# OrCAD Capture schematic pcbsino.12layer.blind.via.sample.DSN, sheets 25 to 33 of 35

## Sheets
25 Pg18: Gbit Ethernet #1: size C
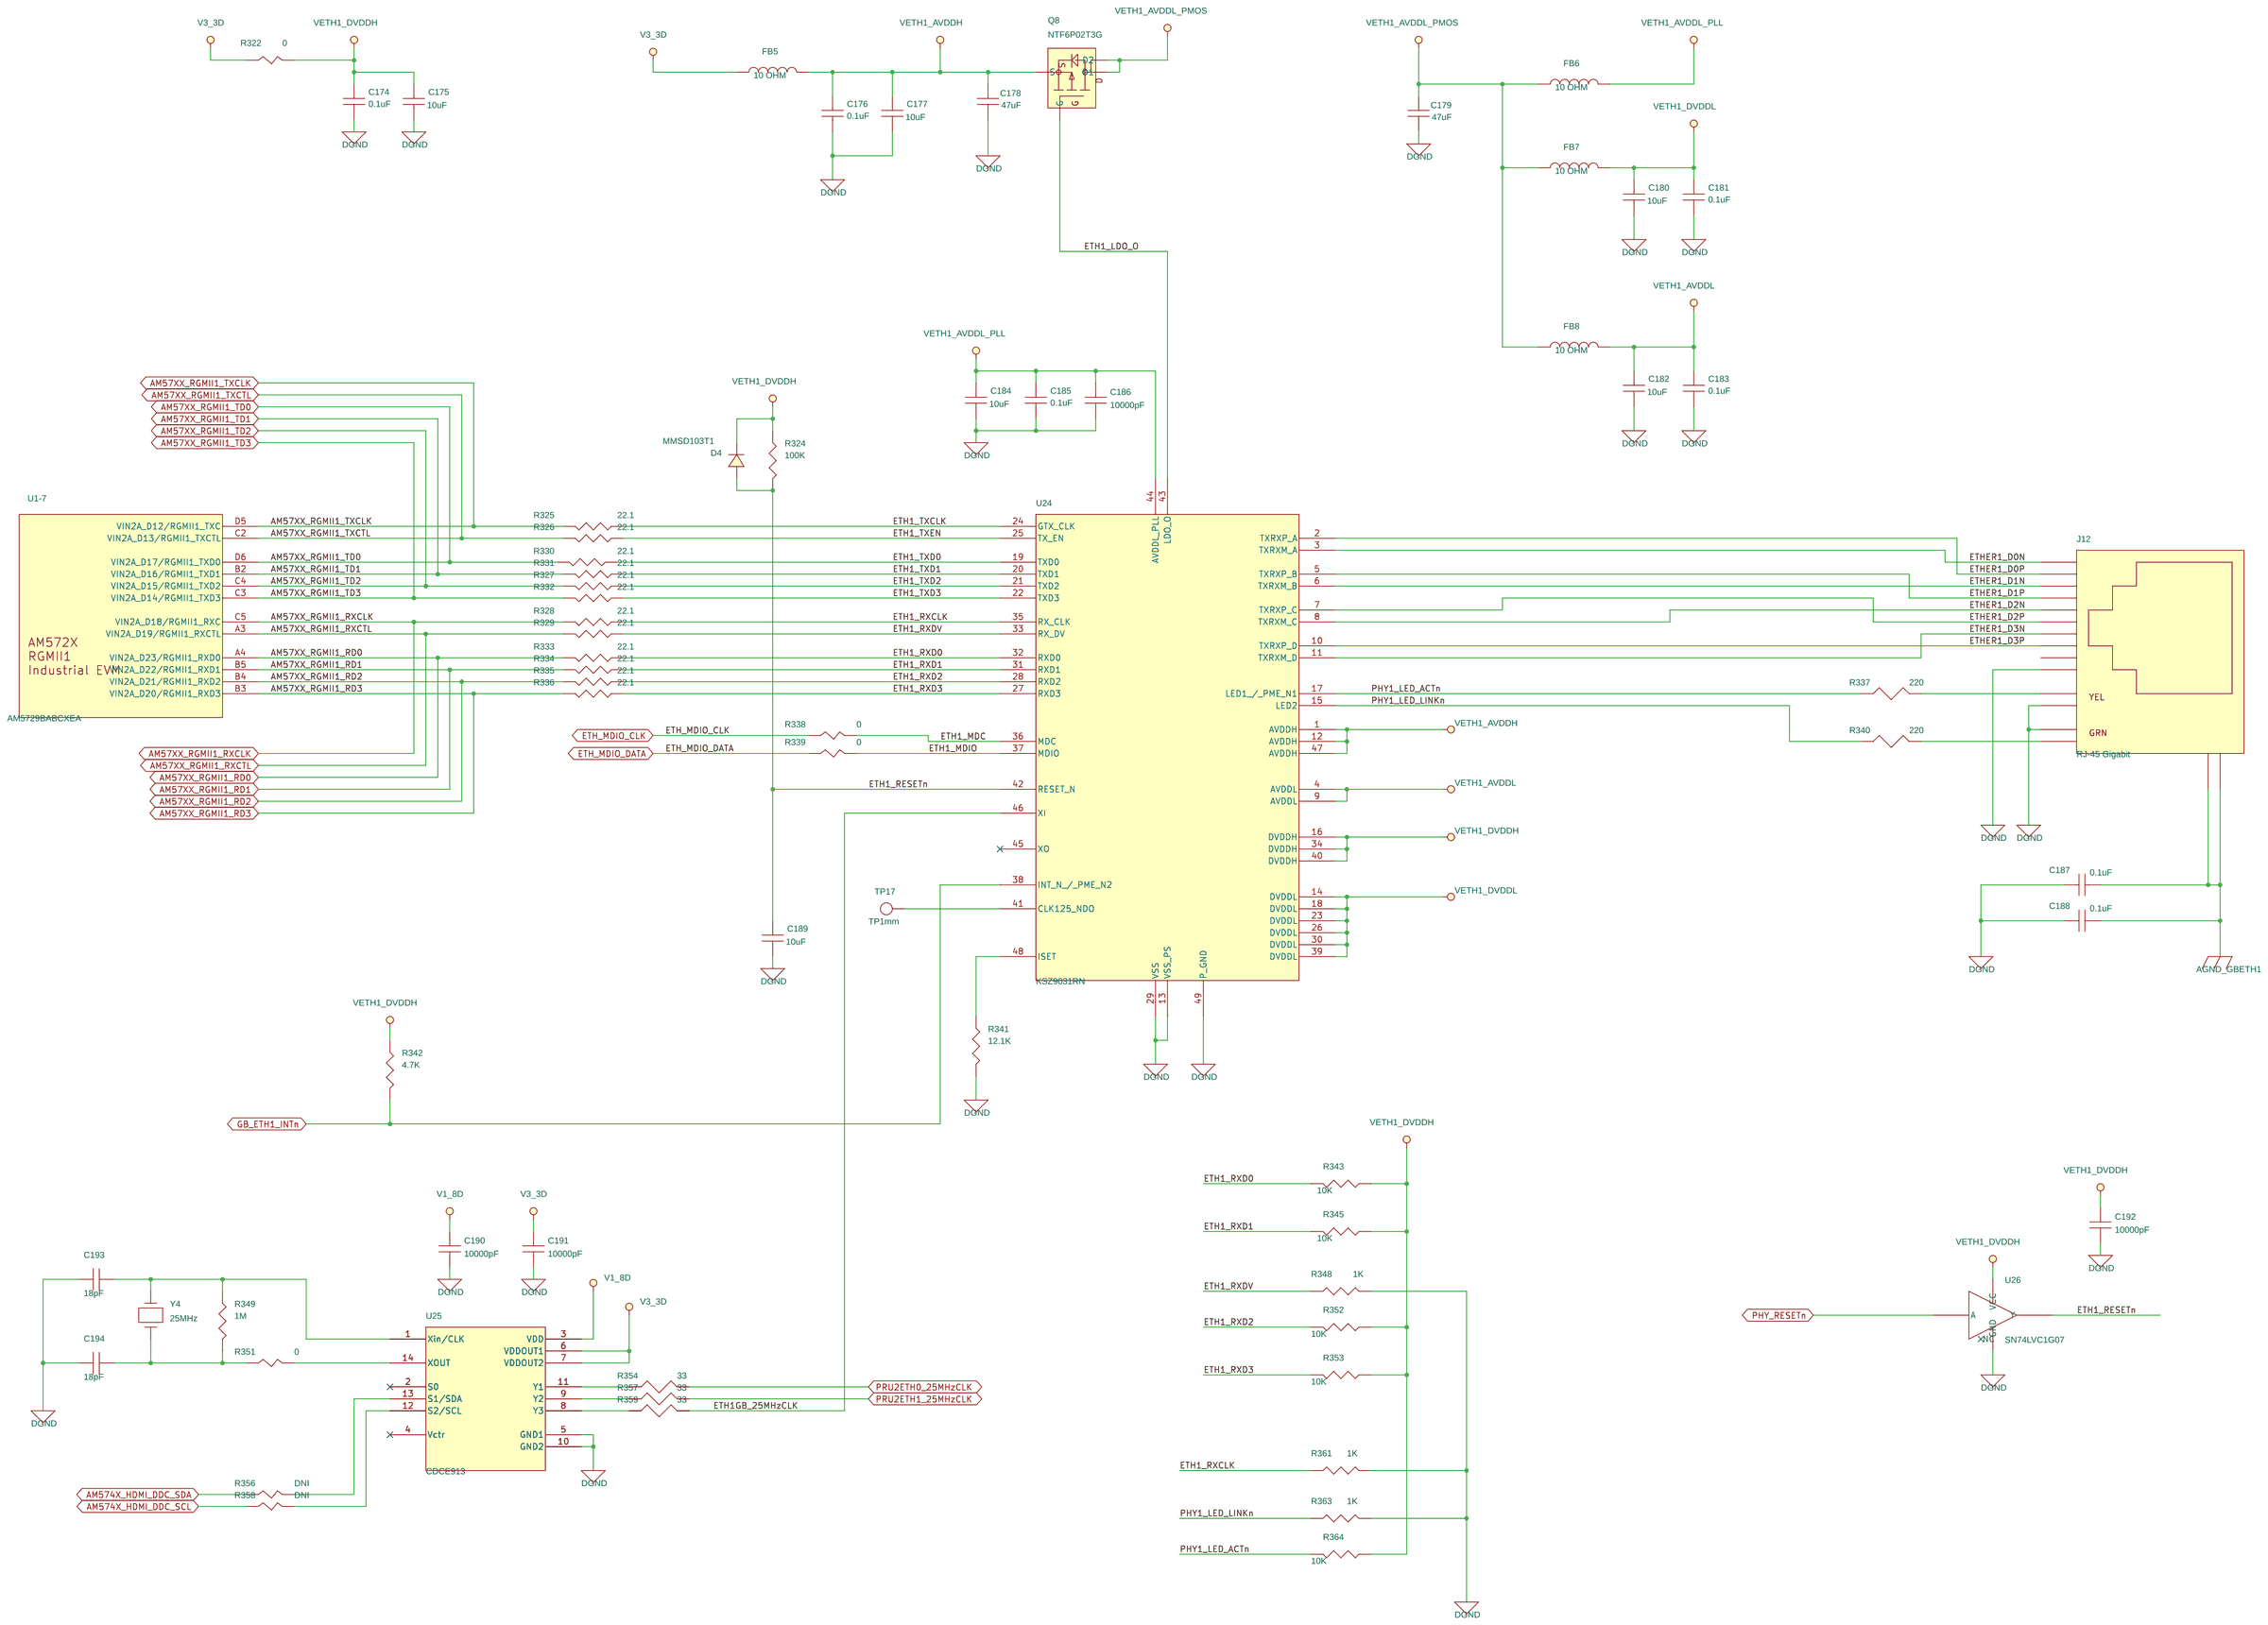
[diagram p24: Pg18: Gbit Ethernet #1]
26 Pg14: ICSS2 Ethernet 1: size C
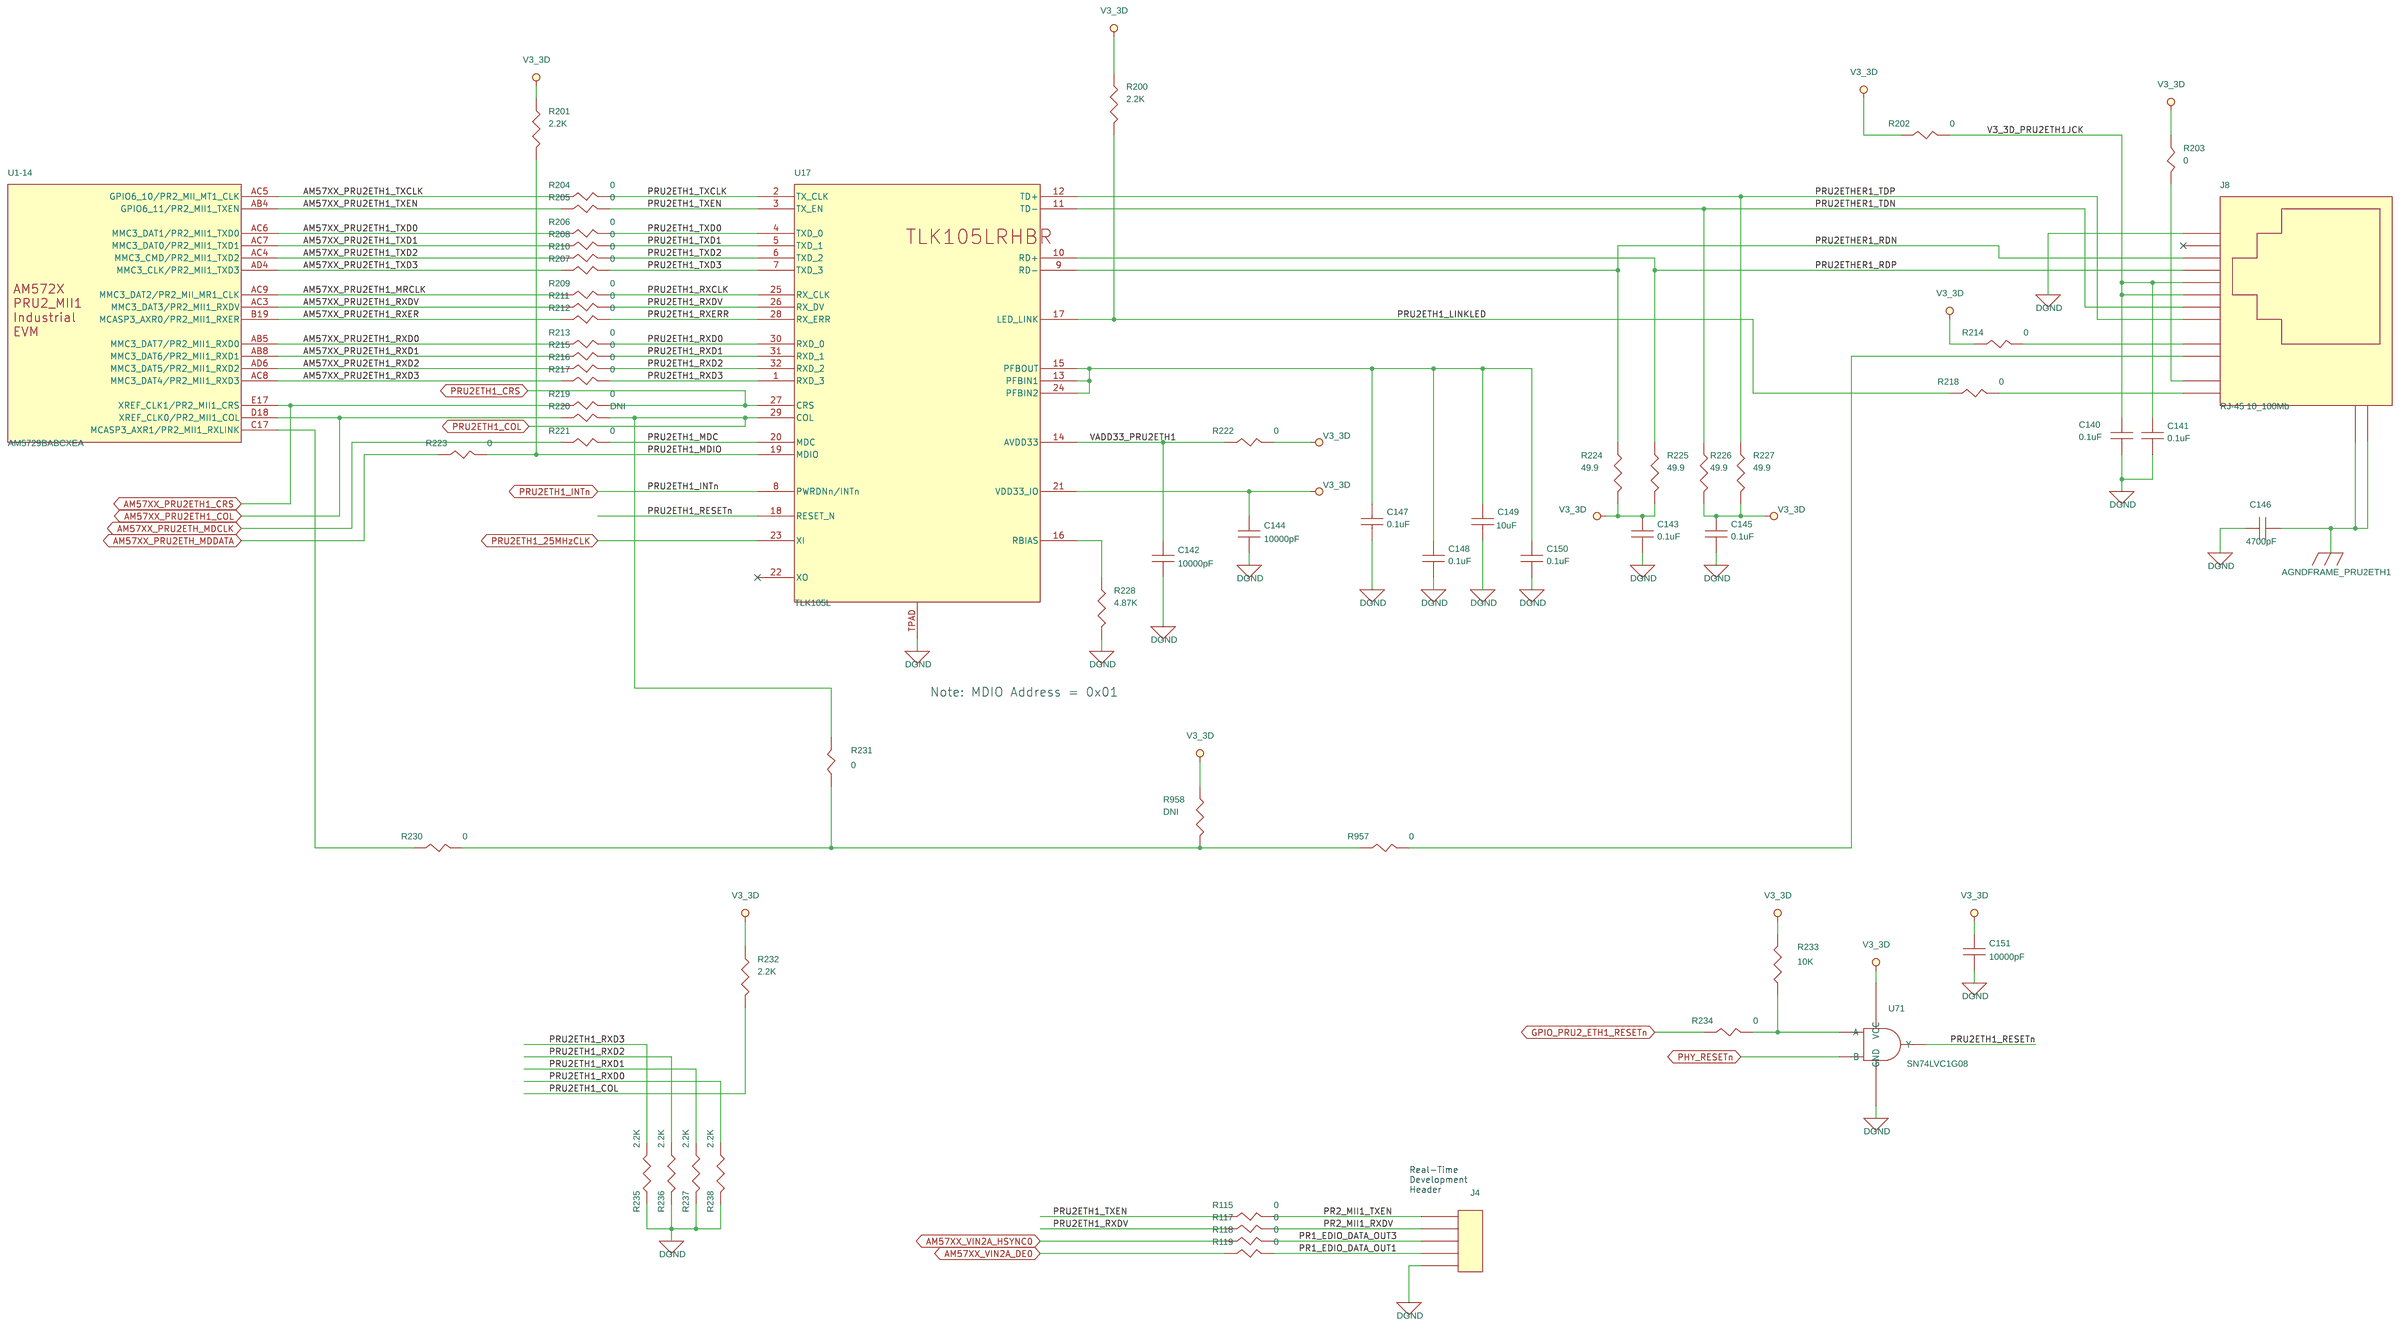
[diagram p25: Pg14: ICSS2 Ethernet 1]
27 Pg13: ICSS2 Ethernet 0: size C
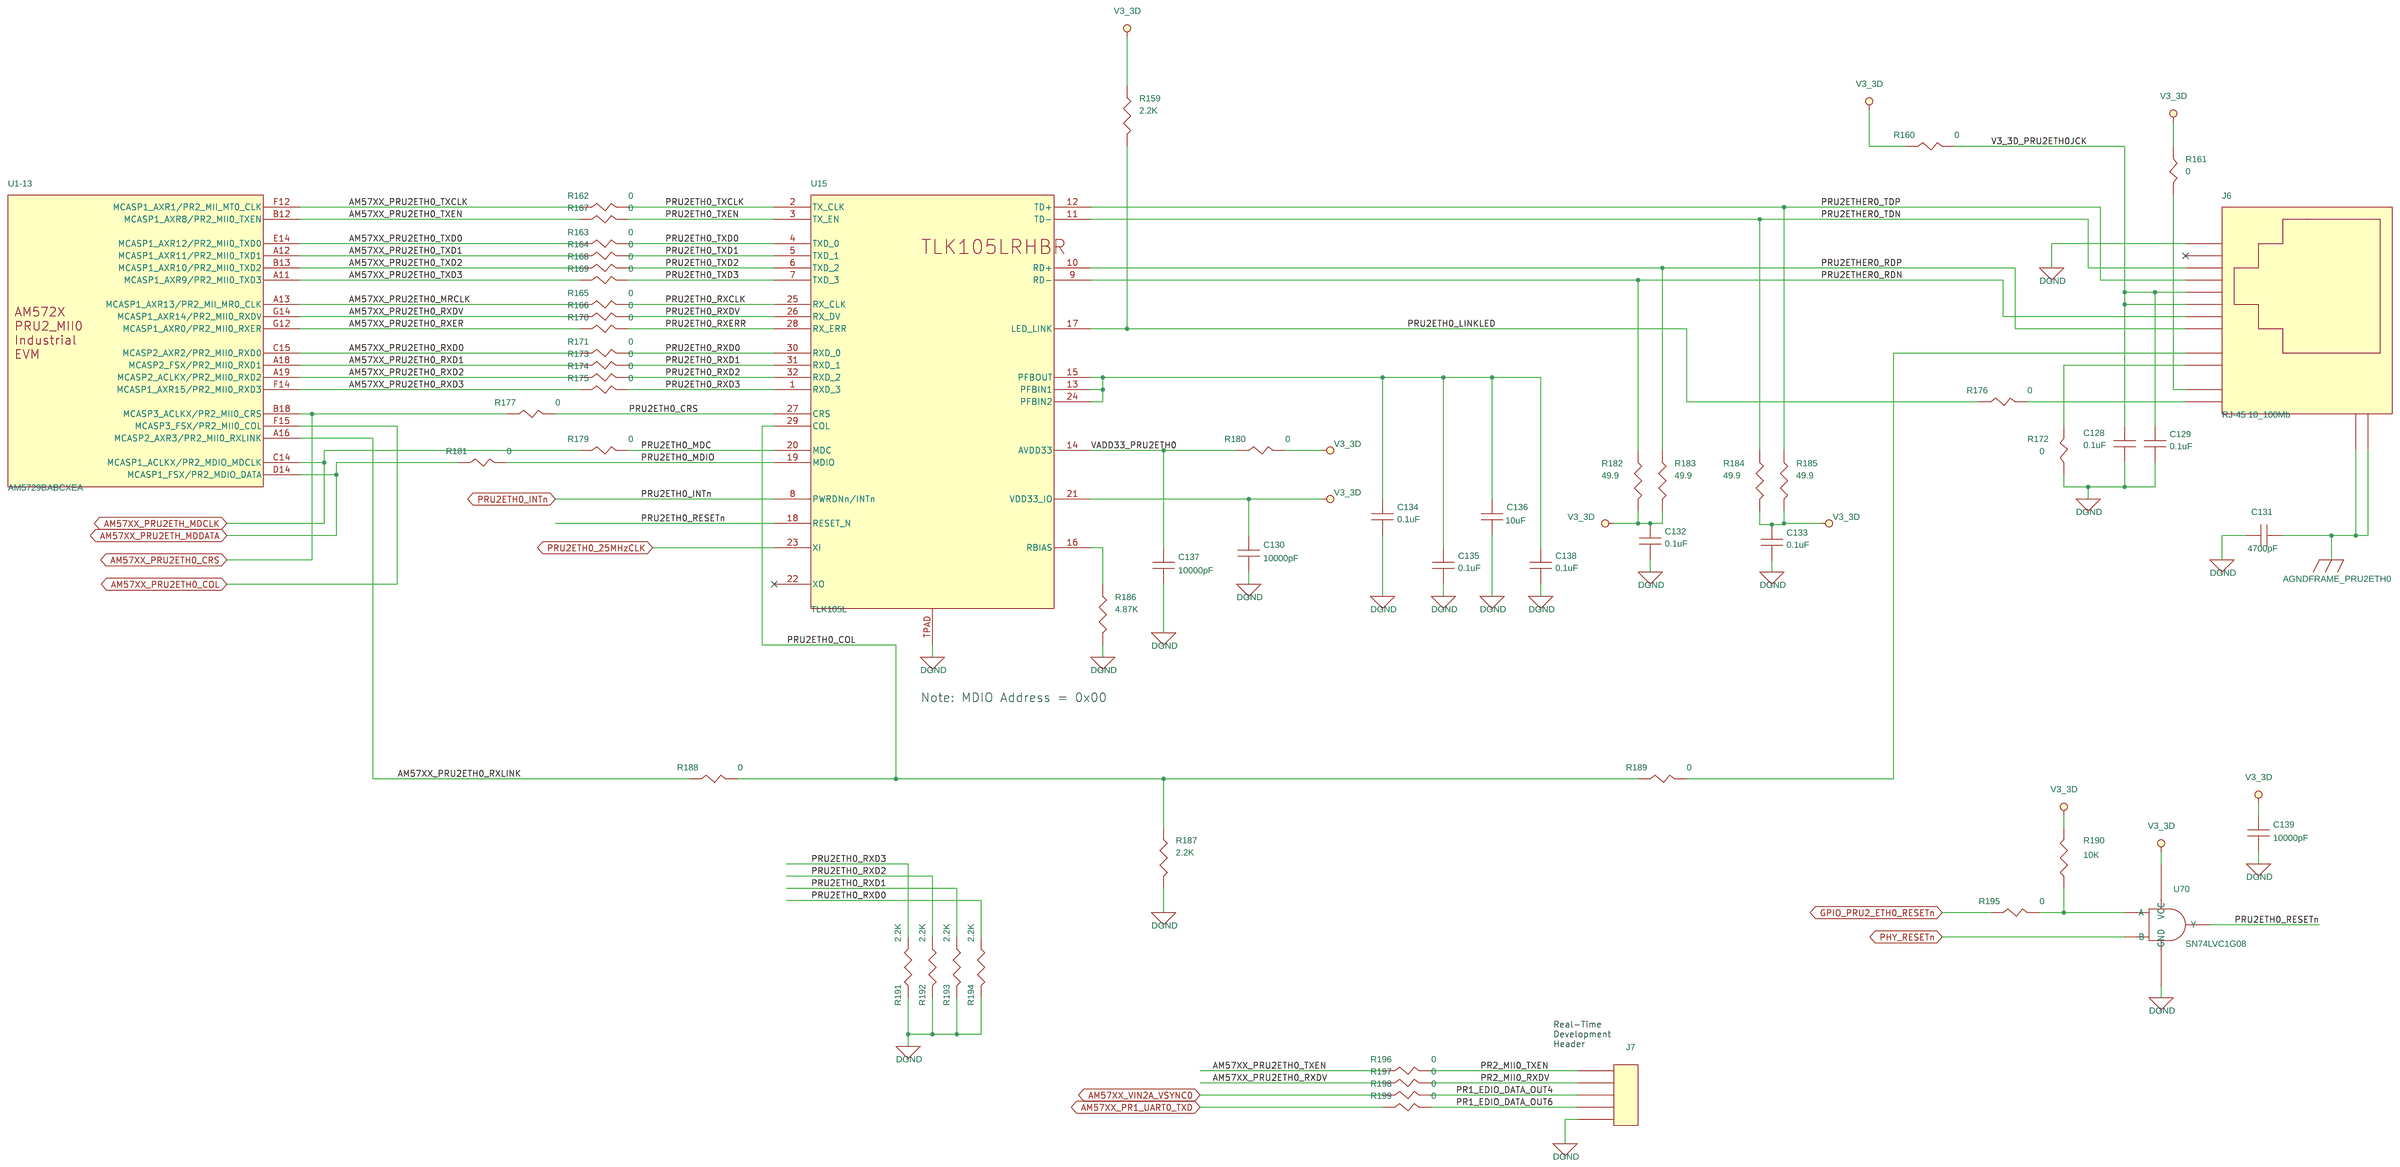
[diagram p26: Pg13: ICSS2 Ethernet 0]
28 Pg17: Gbit Ethernet #0: size C
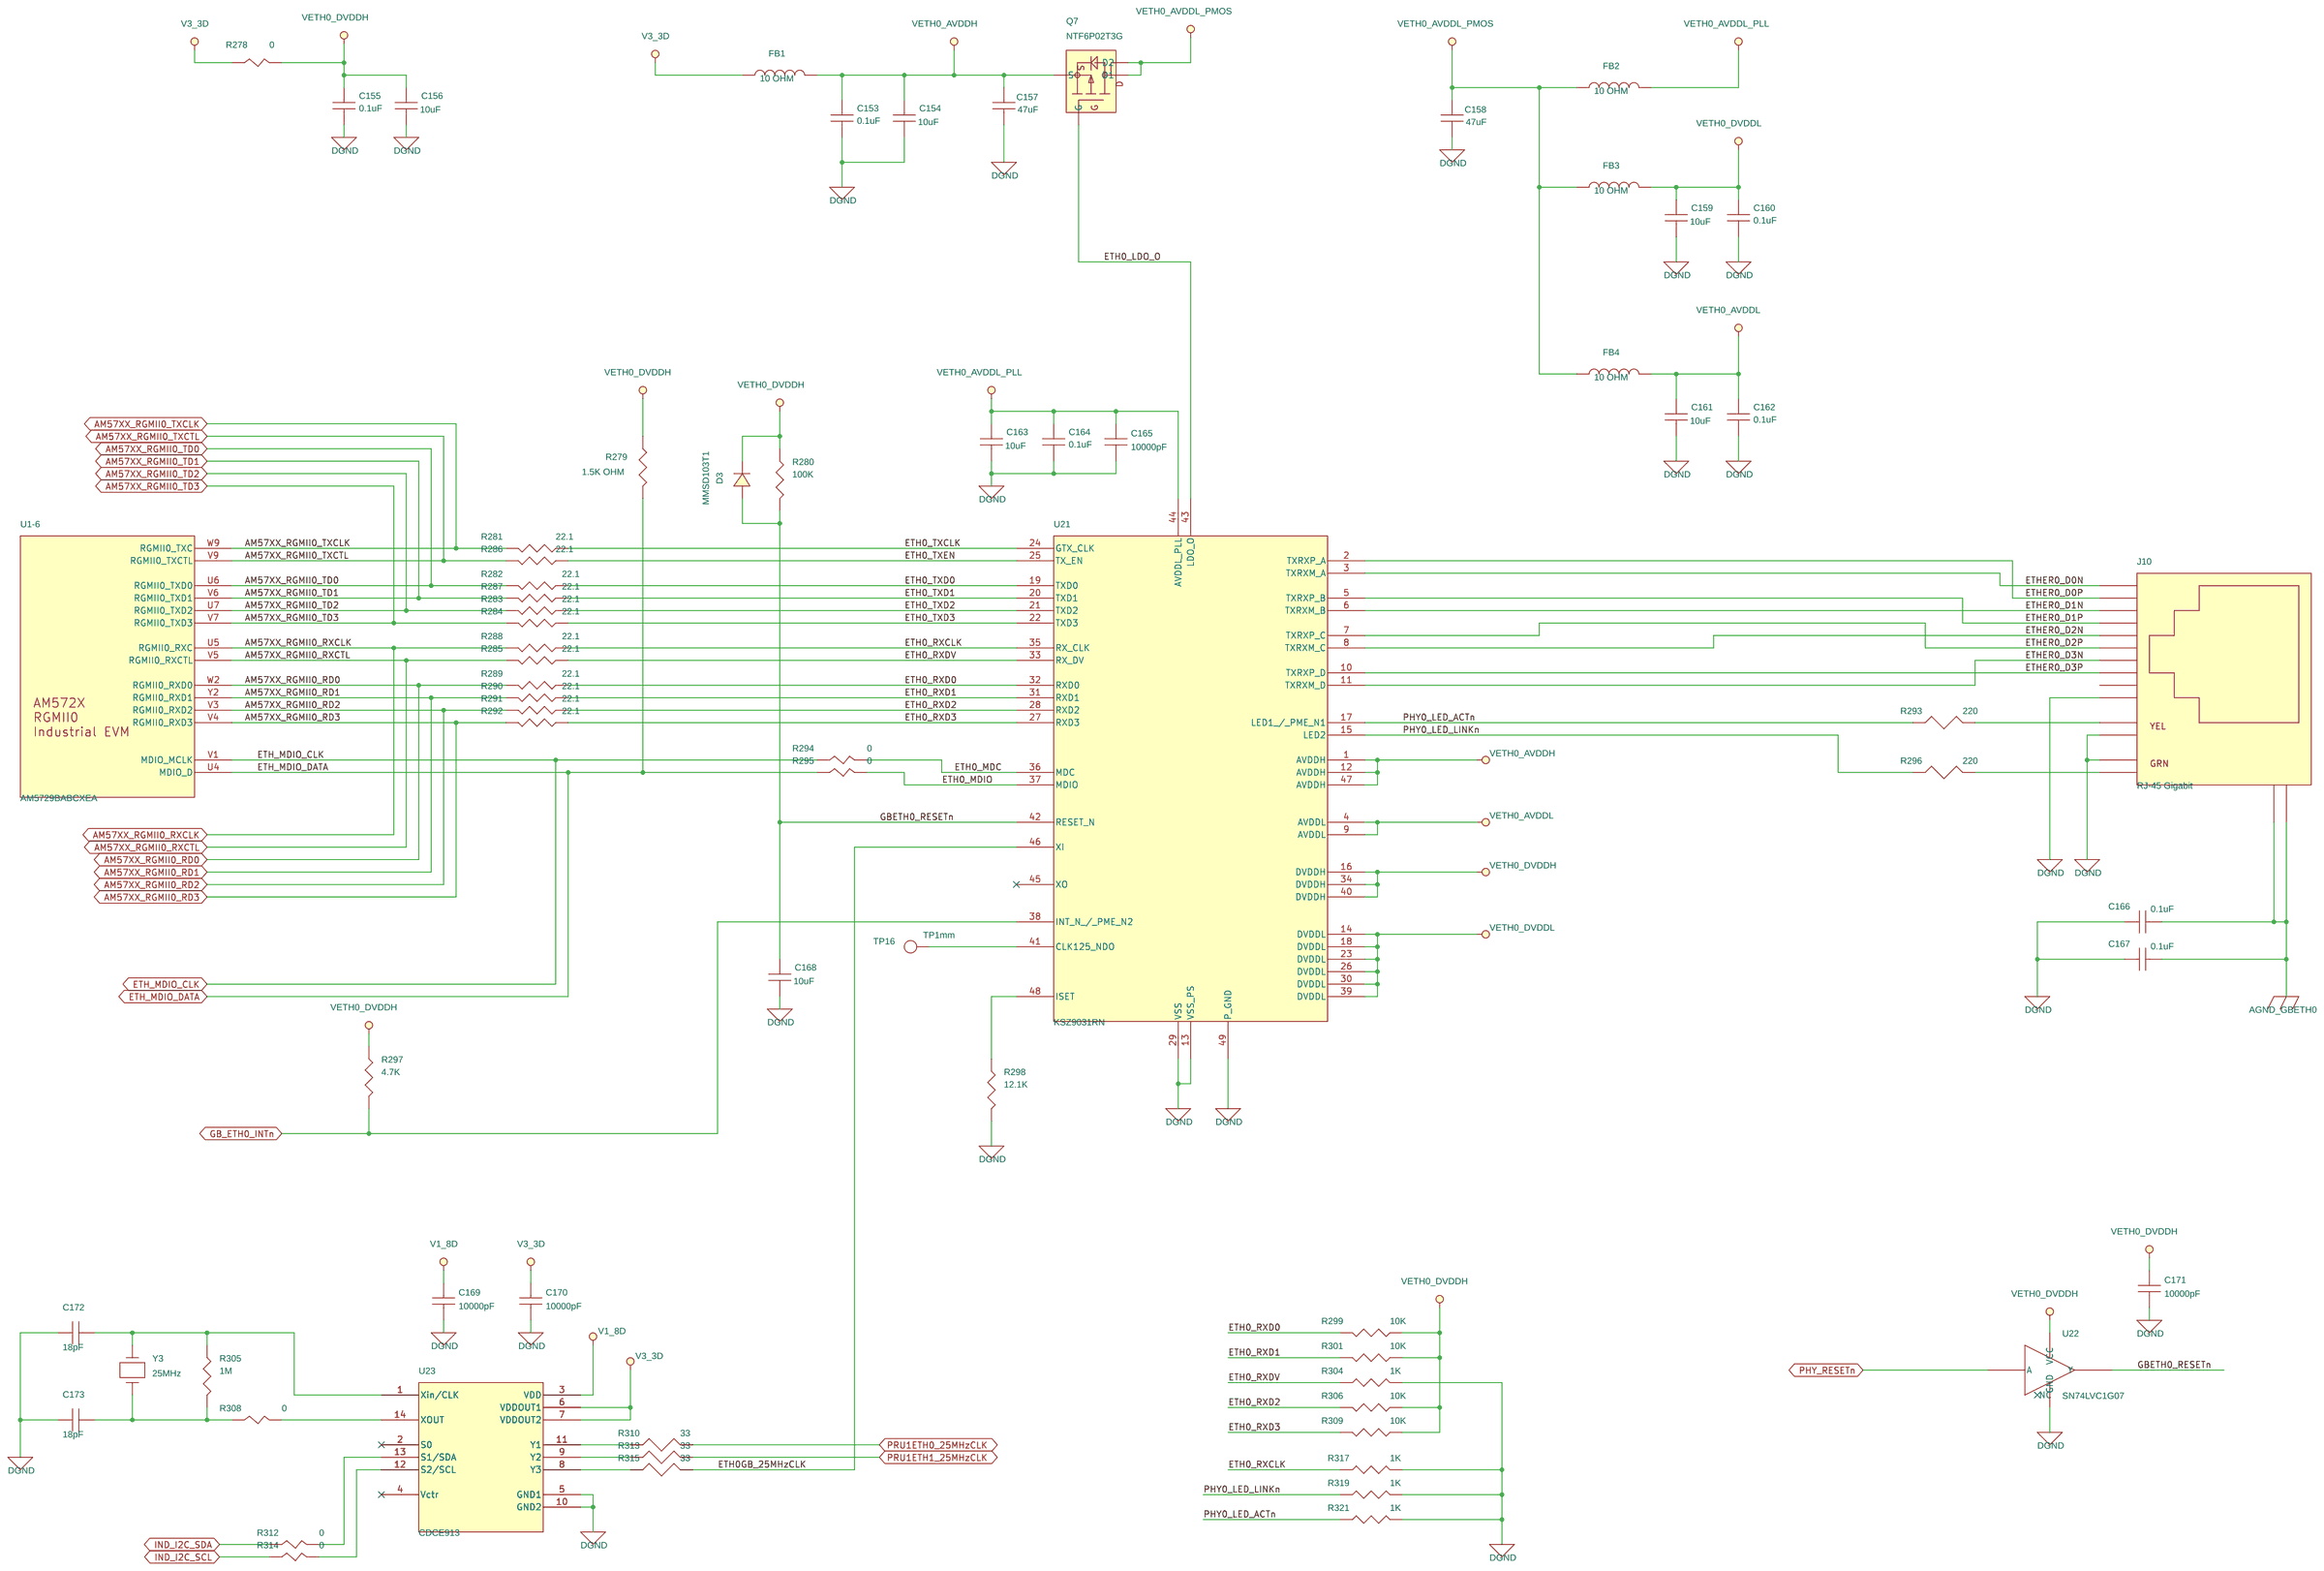
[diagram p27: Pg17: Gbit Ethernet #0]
29 Pg32: RTC & VPP Circuit: size C
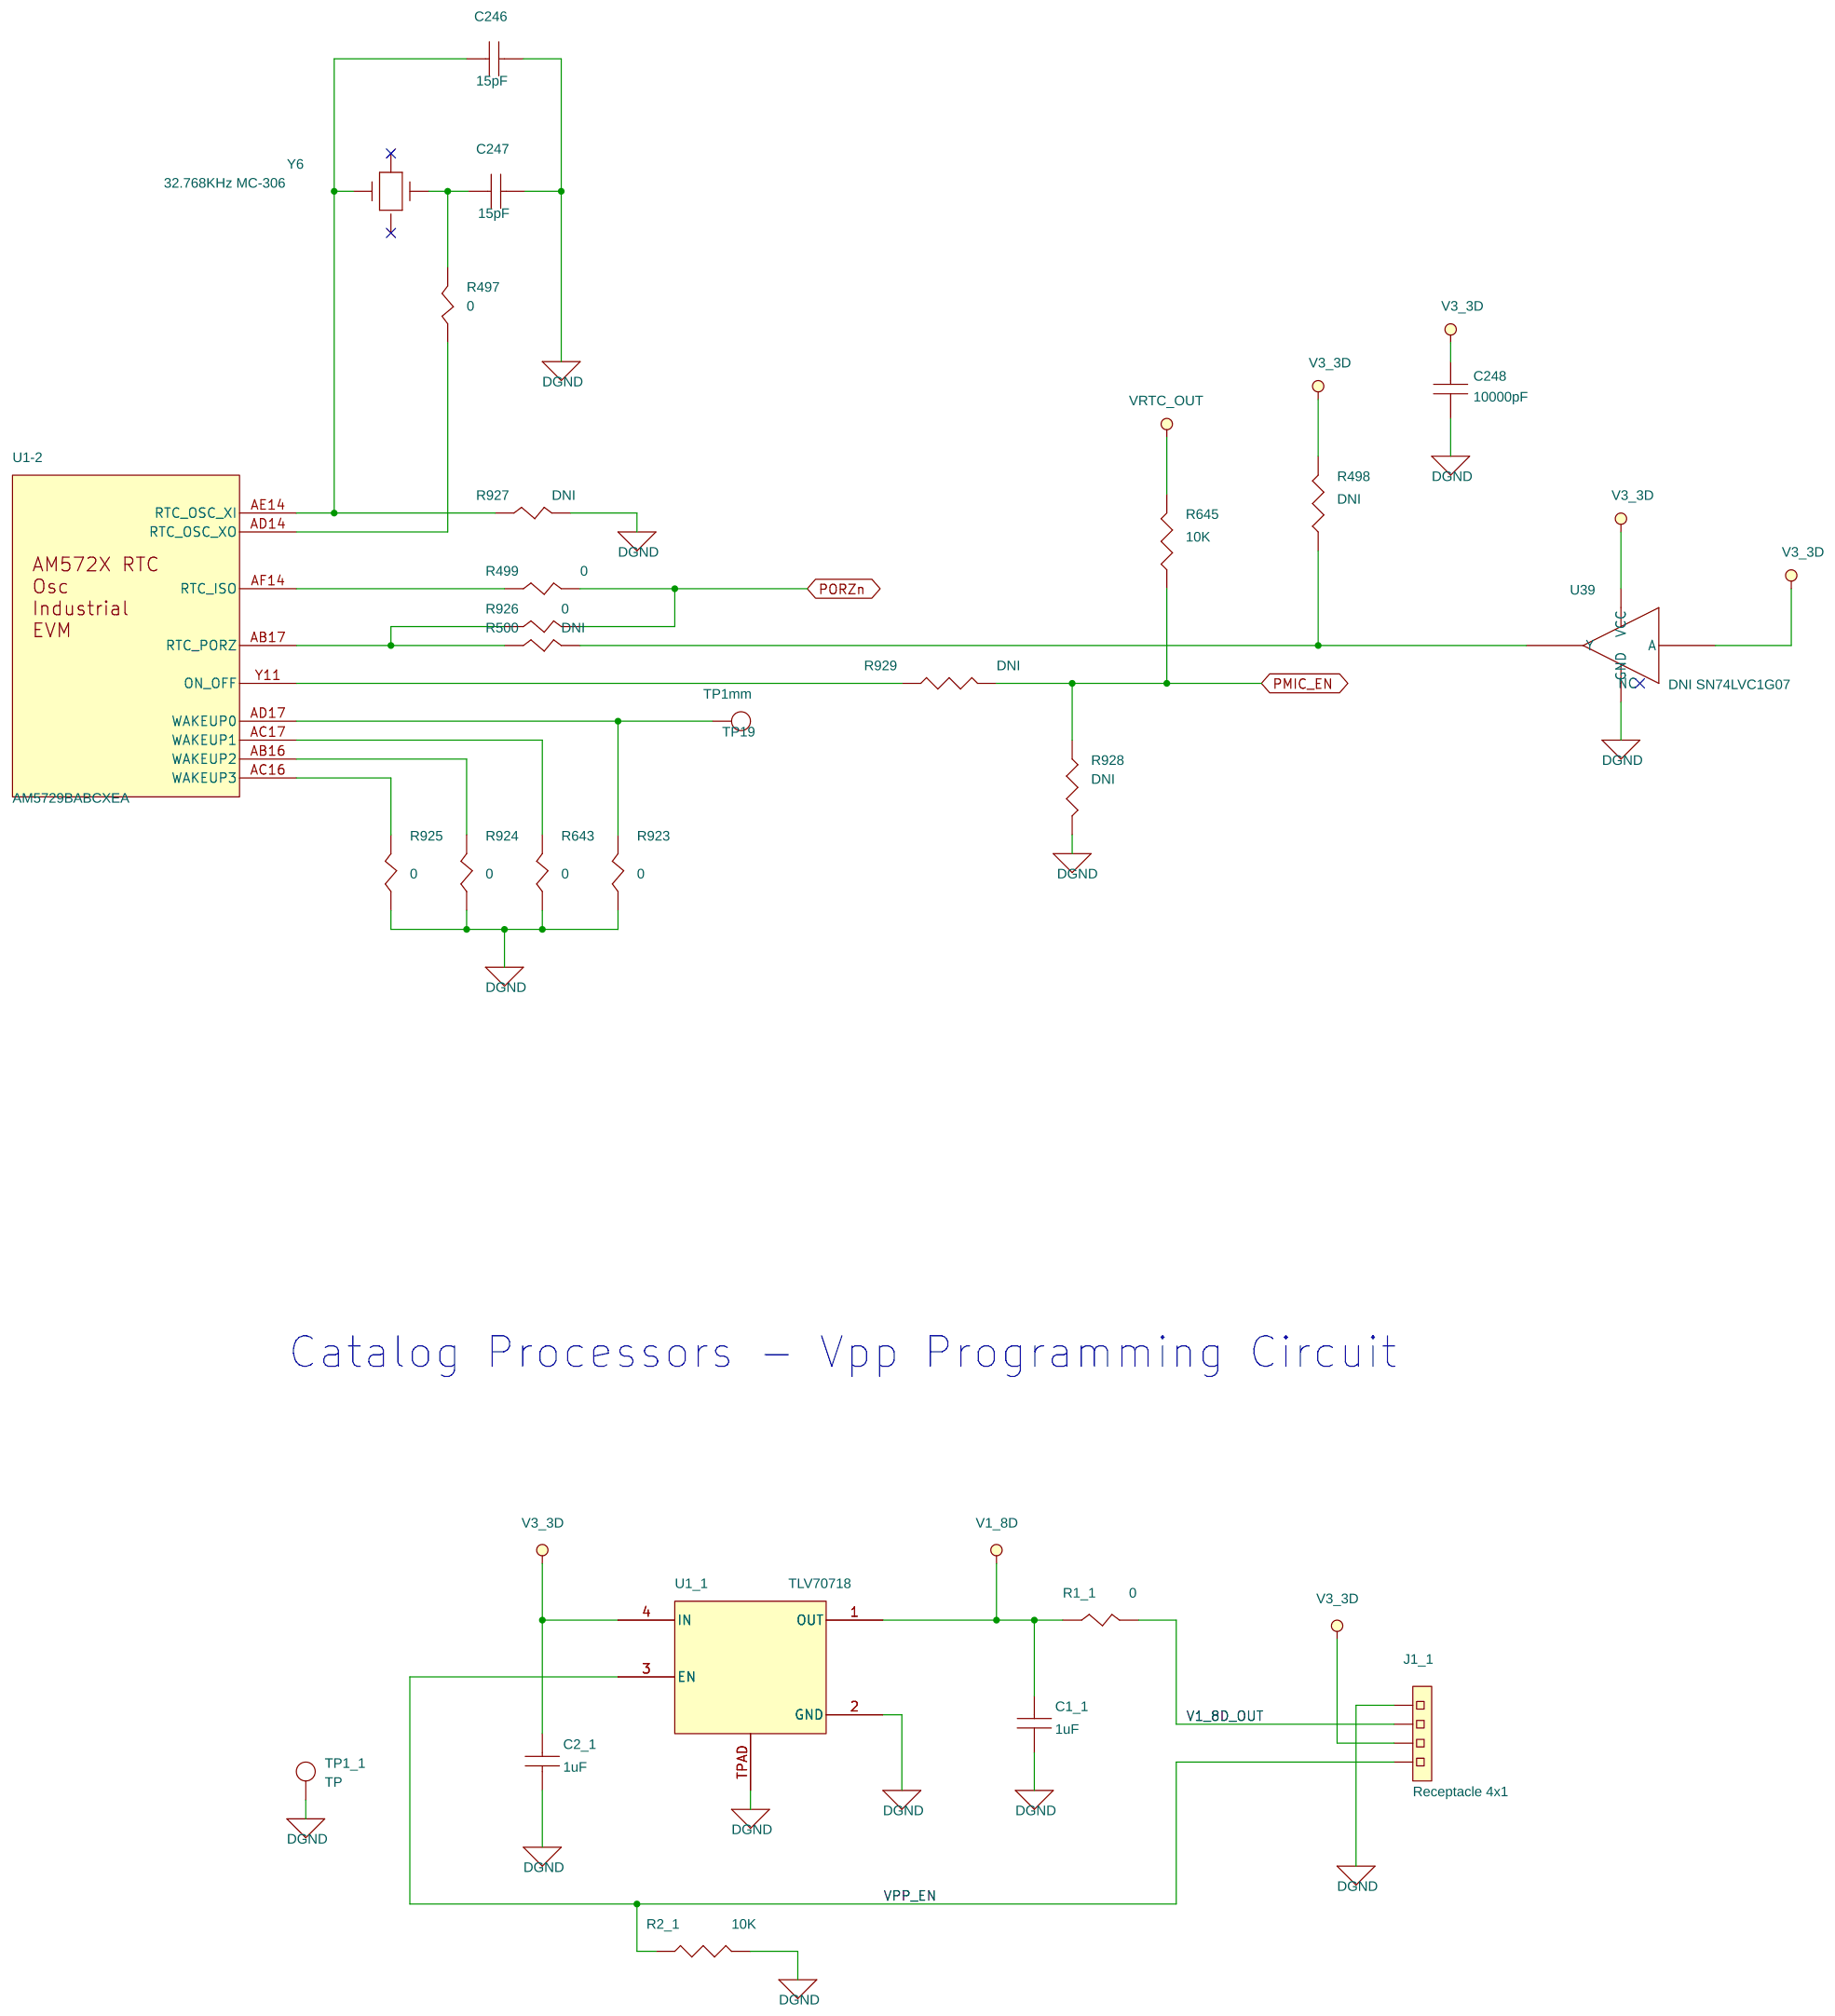
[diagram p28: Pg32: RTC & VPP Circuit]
30 Pg07: QSPI Flash Memory: size C
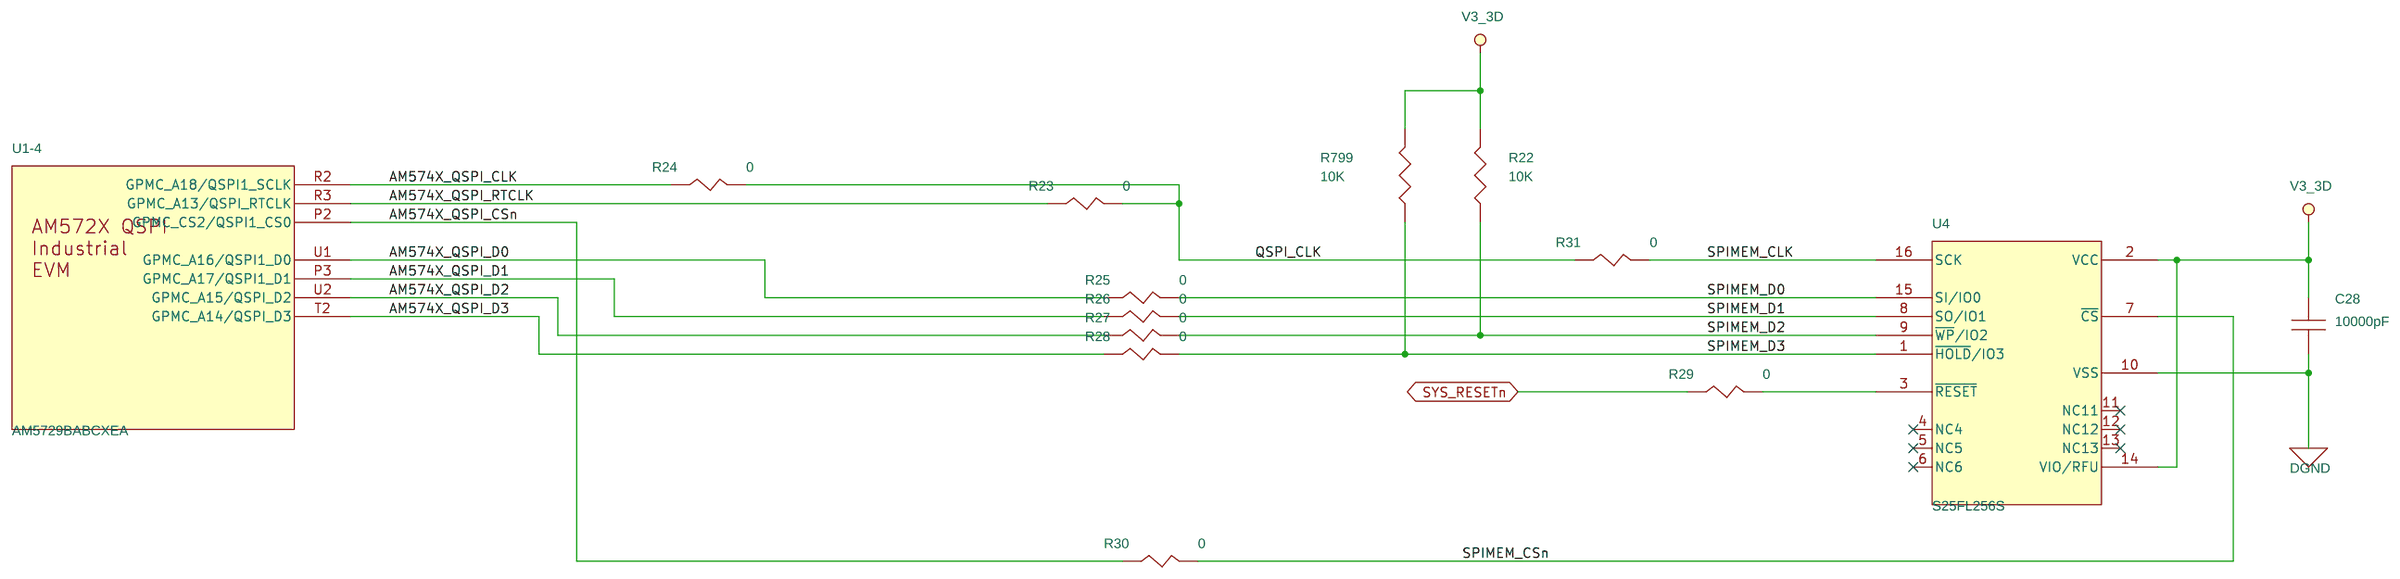
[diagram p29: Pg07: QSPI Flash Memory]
31 Pg02: Processor subsystem: size C
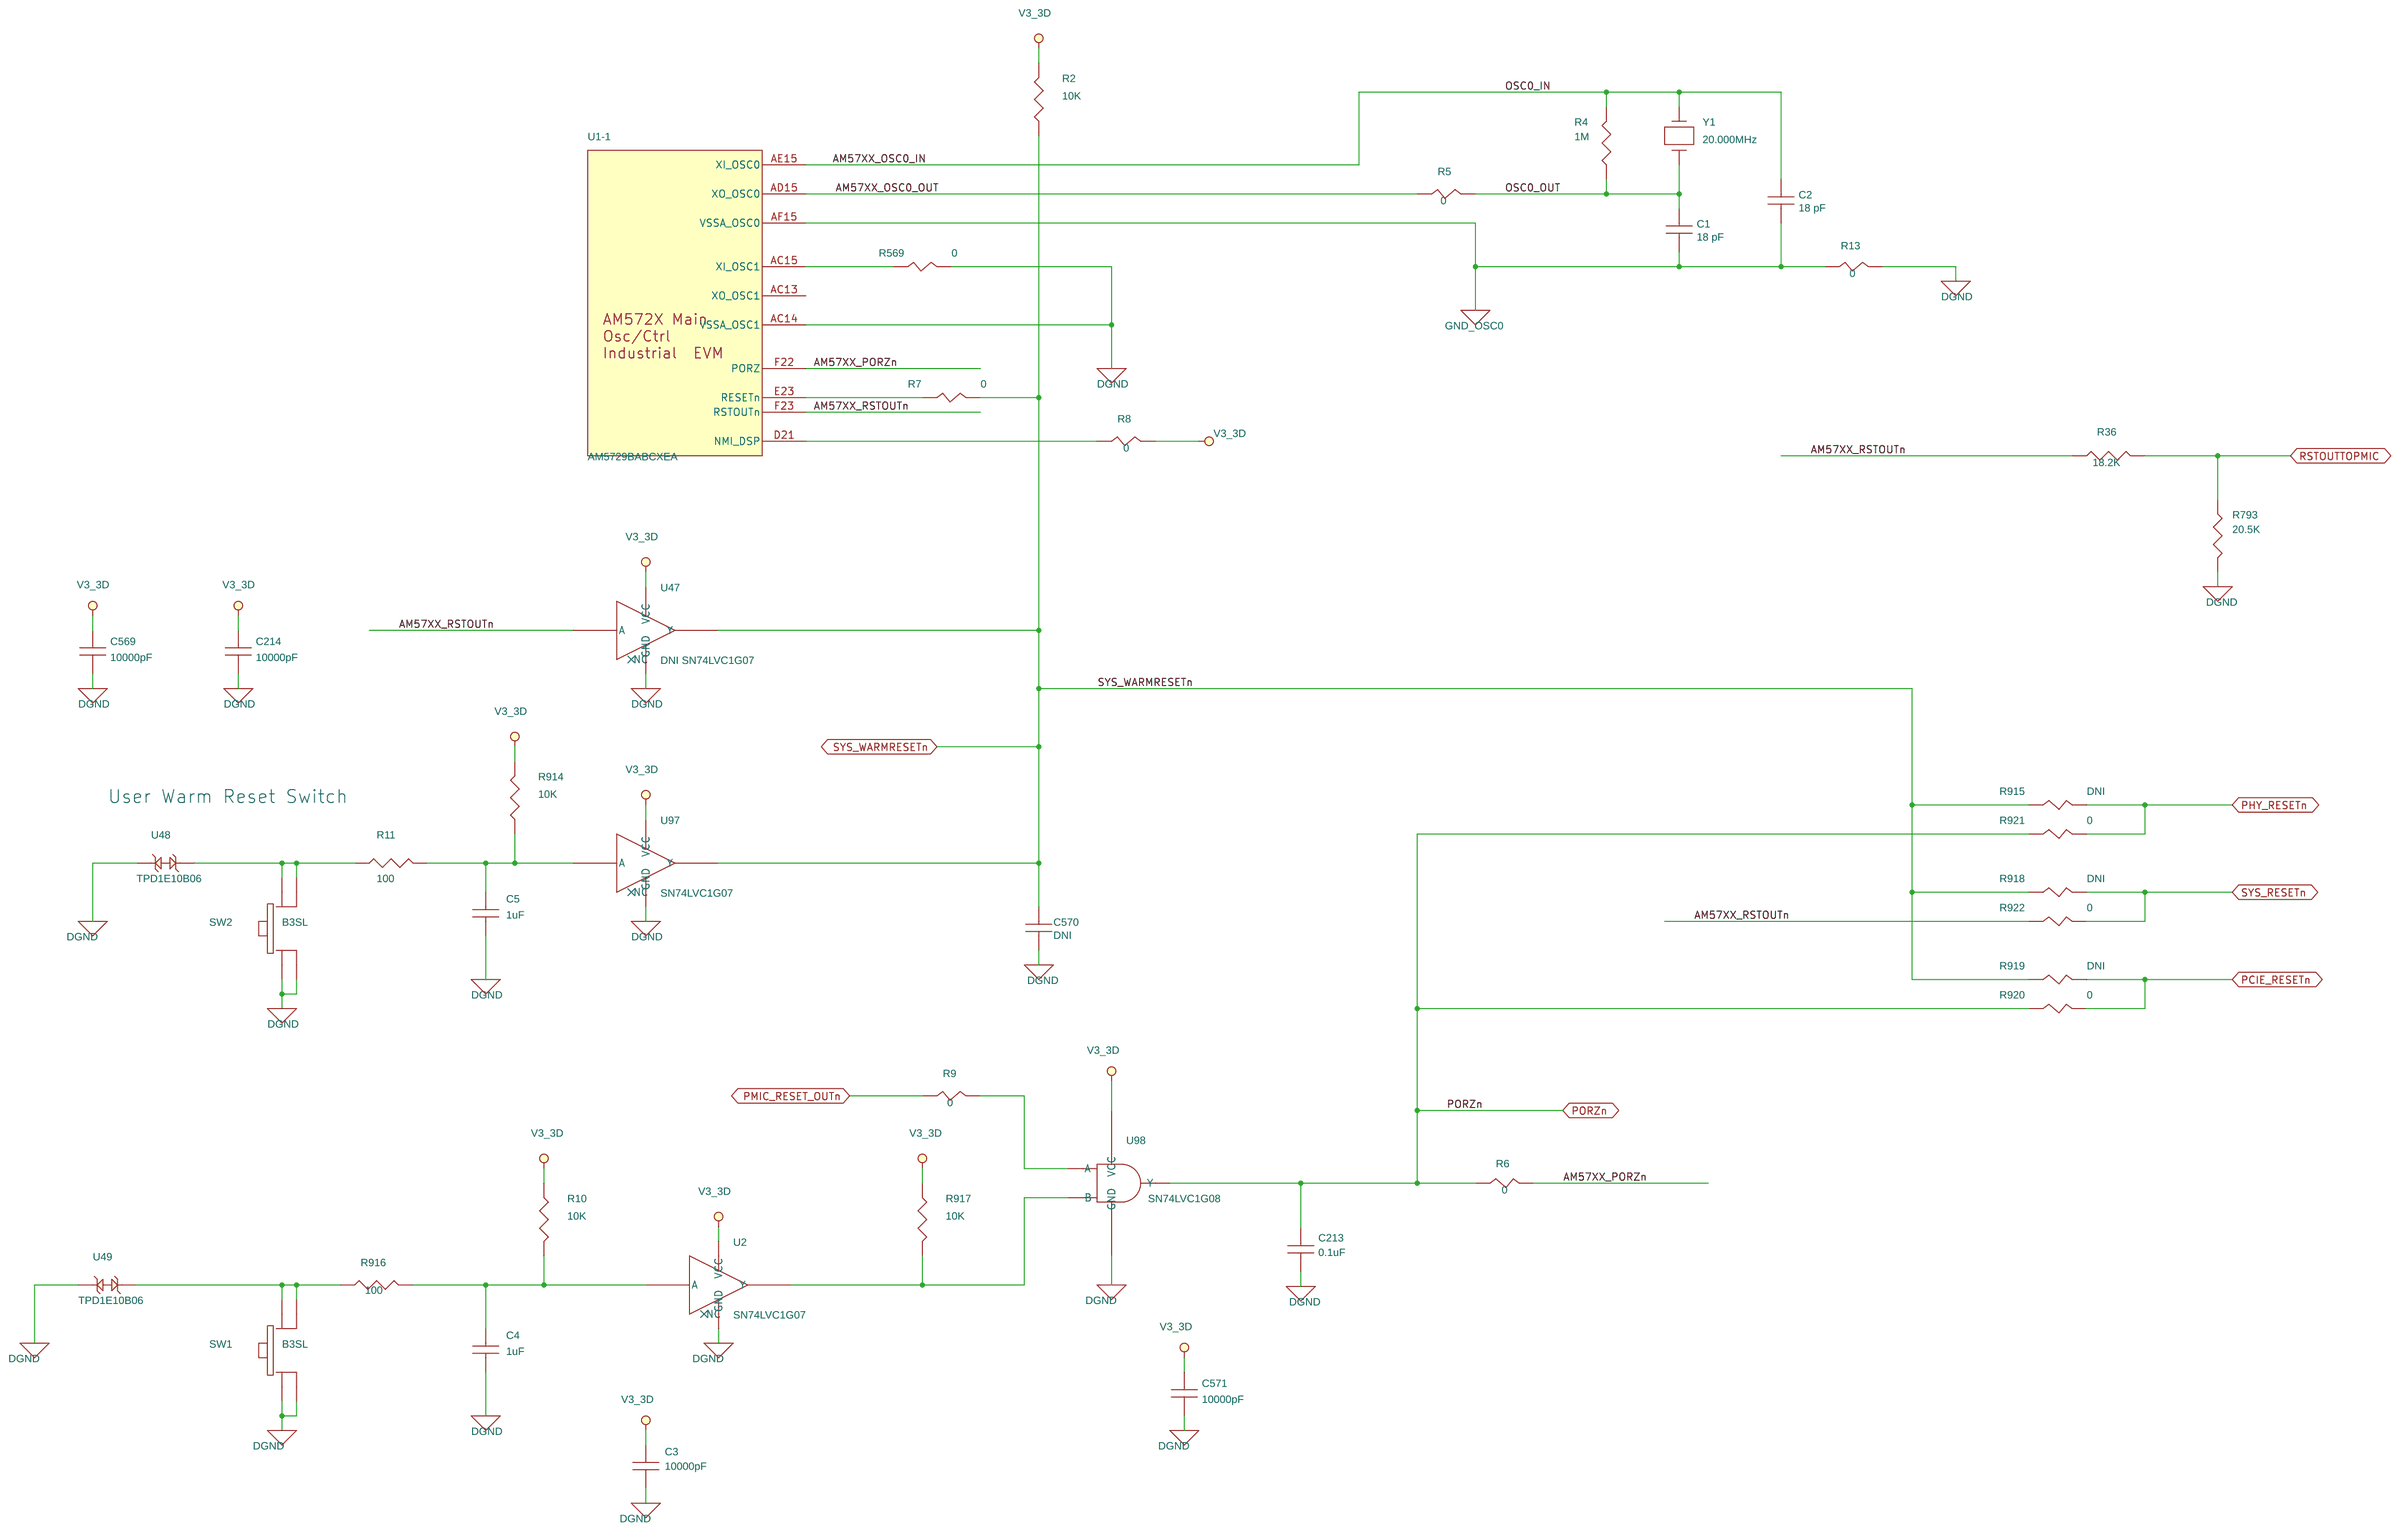
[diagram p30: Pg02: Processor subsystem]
32 Pg19: SDMMC #1 Interface: size C
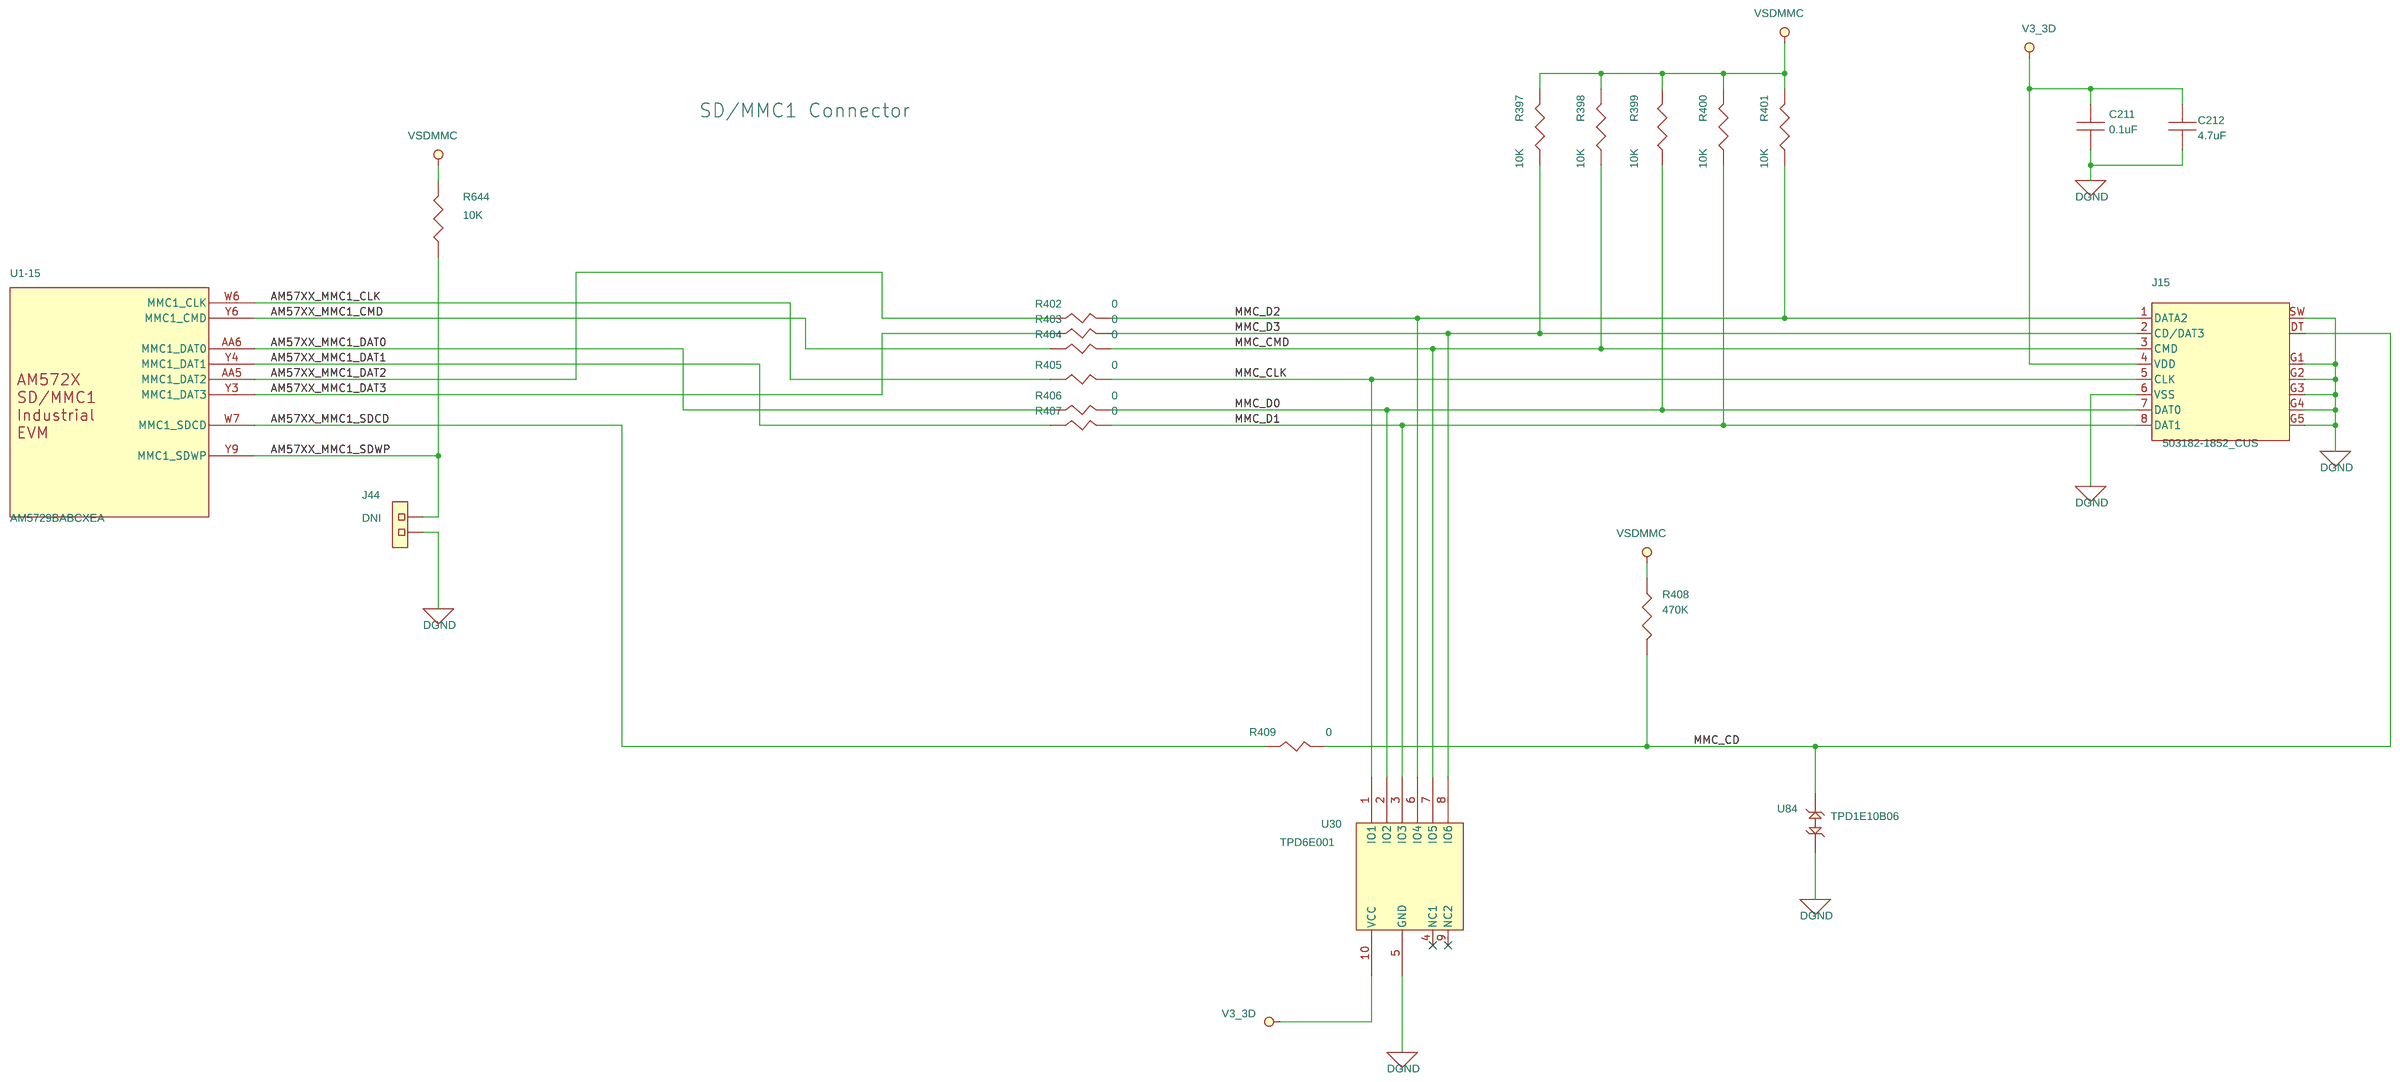
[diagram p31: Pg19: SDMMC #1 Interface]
33 Pg04: Processor Pwr Decoupling: size C
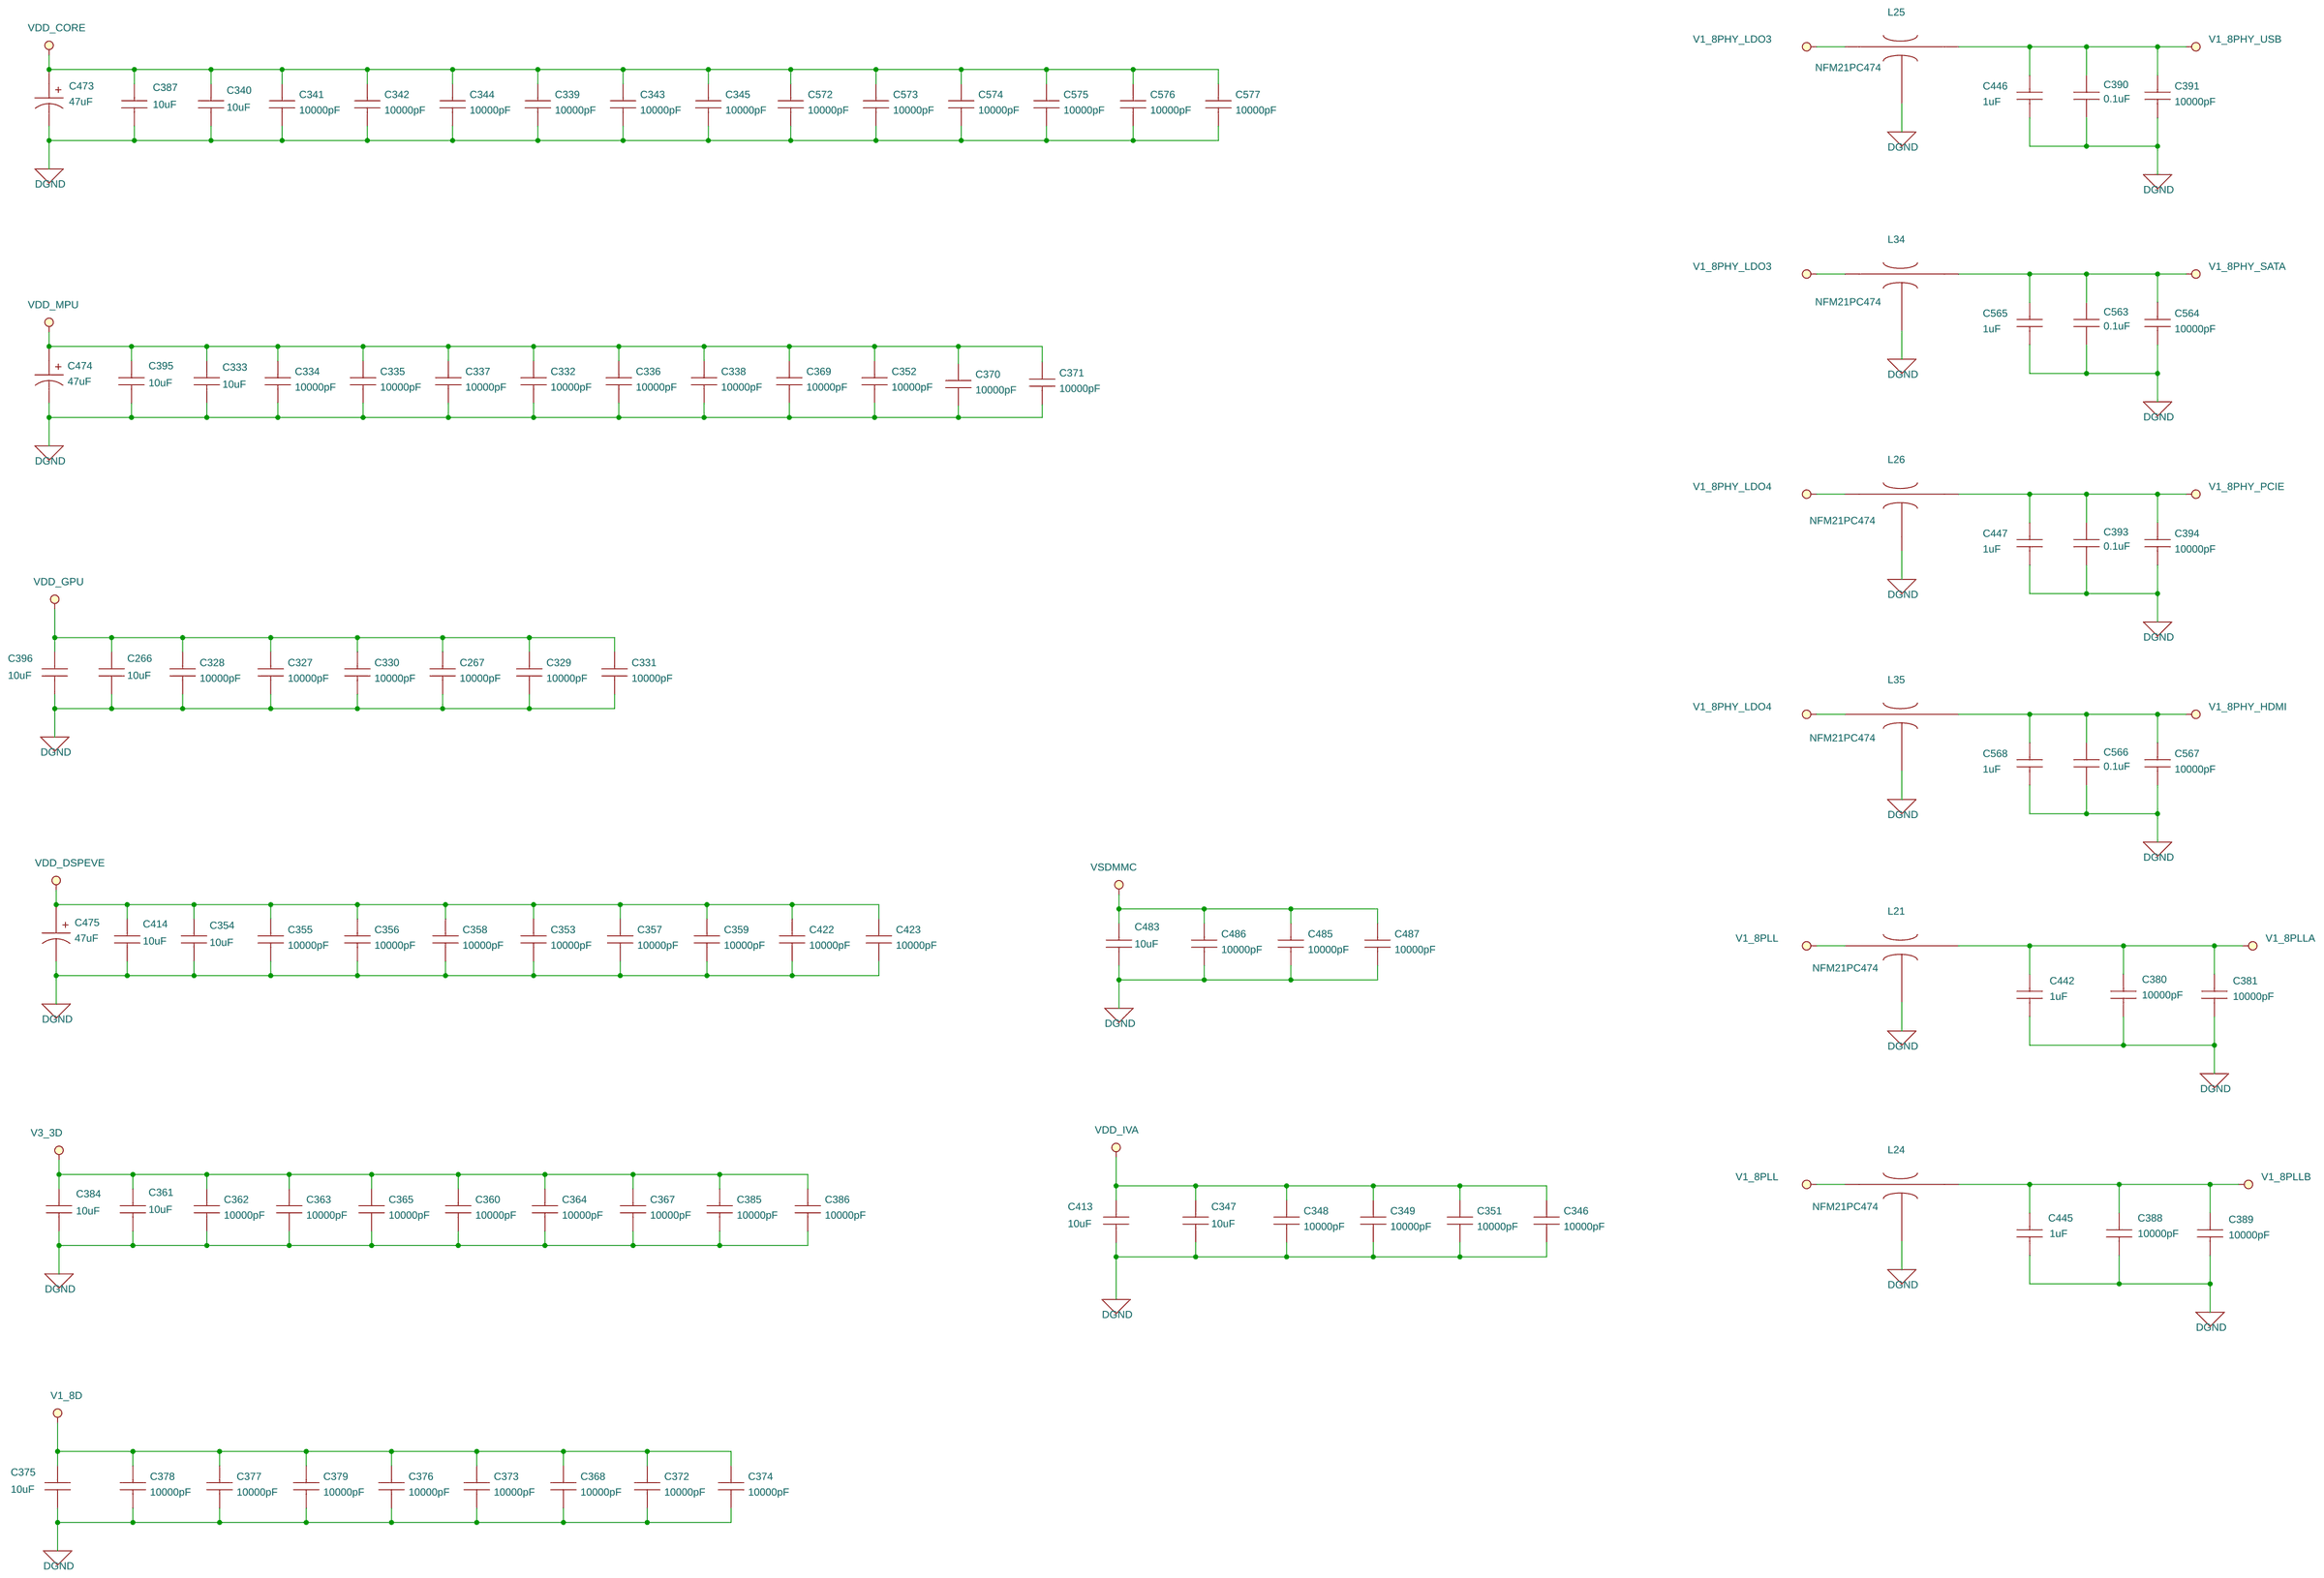
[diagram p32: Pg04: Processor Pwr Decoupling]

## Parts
sheet Pg02: Processor subsystem
C1  18 pF  [CC0402]
C2  18 pF  [CC0402]
C3  10000pF  [CC0402]
C4  1uF  [CC0402]
C5  1uF  [CC0402]
C213  0.1uF  [CC0402]
C214  10000pF  [CC0402]
C569  10000pF  [CC0402]
C570  DNI  [SM-7351-CAP-0402]
C571  10000pF  [CC0402]
R2  10K  [SM-7351-RES-0402]
R4  1M  [SM-7351-RES-0402]
R5  0  [SM-7351-RES-0402]
R6  0  [SM-7351-RES-0402]
R7  0  [SM-7351-RES-0402]
R8  0  [SM-7351-RES-0402]
R9  0  [SM-7351-RES-0402]
R10  10K  [SM-7351-RES-0402]
R11  100  [SM-7351-RES-0402]
R13  0  [SM-7351-RES-0402]
R36  18.2K  [SM-7351-RES-0402]
R569  0  [SM-7351-RES-0402]
R793  20.5K  [SM-7351-RES-0402]
R914  10K  [SM-7351-RES-0402]
R915  DNI  [SM-7351-RES-0402]
R916  100  [SM-7351-RES-0402]
R917  10K  [SM-7351-RES-0402]
R918  DNI  [SM-7351-RES-0402]
R919  DNI  [SM-7351-RES-0402]
R920  0  [SM-7351-RES-0402]
R921  0  [SM-7351-RES-0402]
R922  0  [SM-7351-RES-0402]
SW1  B3SL  [SW_B3SL-1022P]
SW2  B3SL  [SW_B3SL-1022P]
U2  SN74LVC1G07  [u_5_dck]
U47  DNI SN74LVC1G07  [u_5_dck]
U48  TPD1E10B06  [tpd1e10b06-2l]
U49  TPD1E10B06  [tpd1e10b06-2l]
U97  SN74LVC1G07  [u_5_dck]
U98  SN74LVC1G08  [sm-so-sc70-5]
Y1  20.000MHz  [XTAL_ABM7]
sheet Pg04: Processor Pwr Decoupling
C266  10uF  [CC0805]
C267  10000pF  [CC0402]
C327  10000pF  [CC0402]
C328  10000pF  [CC0402]
C329  10000pF  [CC0402]
C330  10000pF  [CC0402]
C331  10000pF  [CC0402]
C332  10000pF  [CC0402]
C333  10uF  [CC0805]
C334  10000pF  [CC0402]
C335  10000pF  [CC0402]
C336  10000pF  [CC0402]
C337  10000pF  [CC0402]
C338  10000pF  [CC0402]
C339  10000pF  [CC0402]
C340  10uF  [CC0805]
C341  10000pF  [CC0402]
C342  10000pF  [CC0402]
C343  10000pF  [CC0402]
C344  10000pF  [CC0402]
C345  10000pF  [CC0402]
C346  10000pF  [CC0402]
C347  10uF  [CC0805]
C348  10000pF  [CC0402]
C349  10000pF  [CC0402]
C351  10000pF  [CC0402]
C352  10000pF  [CC0402]
C353  10000pF  [CC0402]
C354  10uF  [CC0805]
C355  10000pF  [CC0402]
C356  10000pF  [CC0402]
C357  10000pF  [CC0402]
C358  10000pF  [CC0402]
C359  10000pF  [CC0402]
C360  10000pF  [CC0402]
C361  10uF  [CC0805]
C362  10000pF  [CC0402]
C363  10000pF  [CC0402]
C364  10000pF  [CC0402]
C365  10000pF  [CC0402]
C367  10000pF  [CC0402]
C368  10000pF  [CC0402]
C369  10000pF  [CC0402]
C370  10000pF  [CC0402]
C371  10000pF  [CC0402]
C372  10000pF  [CC0402]
C373  10000pF  [CC0402]
C374  10000pF  [CC0402]
C375  10uF  [CC0805]
C376  10000pF  [CC0402]
C377  10000pF  [CC0402]
C378  10000pF  [CC0402]
C379  10000pF  [CC0402]
C380  10000pF  [CC0402]
C381  10000pF  [CC0402]
C384  10uF  [CC0805]
C385  10000pF  [CC0402]
C386  10000pF  [CC0402]
C387  10uF  [CC0805]
C388  10000pF  [CC0402]
C389  10000pF  [CC0402]
C390  0.1uF  [CC0402]
C391  10000pF  [CC0402]
C393  0.1uF  [CC0402]
C394  10000pF  [CC0402]
C395  10uF  [CC0805]
C396  10uF  [CC0805]
C413  10uF  [CC0805]
C414  10uF  [CC0805]
C422  10000pF  [CC0402]
C423  10000pF  [CC0402]
C442  1uF  [CC0402]
C445  1uF  [CC0402]
C446  1uF  [CC0402]
C447  1uF  [CC0402]
C473  47uF  [CT7343-31]
C474  47uF  [CT7343-31]
C475  47uF  [CT7343-31]
C483  10uF  [CC0805]
C485  10000pF  [CC0402]
C486  10000pF  [CC0402]
C487  10000pF  [CC0402]
C563  0.1uF  [CC0402]
C564  10000pF  [CC0402]
C565  1uF  [CC0402]
C566  0.1uF  [CC0402]
C567  10000pF  [CC0402]
C568  1uF  [CC0402]
C572  10000pF  [CC0402]
C573  10000pF  [CC0402]
C574  10000pF  [CC0402]
C575  10000pF  [CC0402]
C576  10000pF  [CC0402]
C577  10000pF  [CC0402]
L21  NFM21PC474  [FILT-NFM21PC]
L24  NFM21PC474  [FILT-NFM21PC]
L25  NFM21PC474  [FILT-NFM21PC]
L26  NFM21PC474  [FILT-NFM21PC]
L34  NFM21PC474  [FILT-NFM21PC]
L35  NFM21PC474  [FILT-NFM21PC]
sheet Pg07: QSPI Flash Memory
C28  10000pF  [CC0402]
R22  10K  [SM-7351-RES-0402]
R23  0  [SM-7351-RES-0402]
R24  0  [SM-7351-RES-0402]
R25  0  [SM-7351-RES-0402]
R26  0  [SM-7351-RES-0402]
R27  0  [SM-7351-RES-0402]
R28  0  [SM-7351-RES-0402]
R29  0  [SM-7351-RES-0402]
R30  0  [SM-7351-RES-0402]
R31  0  [SM-7351-RES-0402]
R799  10K  [SM-7351-RES-0402]
U4  S25FL256S  [soic_16pin_dw]
sheet Pg13: ICSS2 Ethernet 0
C128  0.1uF  [CC0402]
C129  0.1uF  [CC0402]
C130  10000pF  [CC0402]
C131  4700pF  [CC0402]
C132  0.1uF  [CC0402]
C133  0.1uF  [CC0402]
C134  0.1uF  [CC0402]
C135  0.1uF  [CC0402]
C136  10uF  [CC0805]
C137  10000pF  [CC0402]
C138  0.1uF  [CC0402]
C139  10000pF  [CC0402]
J6  RJ-45 10_100Mb  [CNRJ45-1X1WLED]
J7  HEADER 5  [HEADER_5X1]
R159  2.2K  [sm-7351-res-0402]
R160  0  [SM-7351-RES-0402]
R161  0  [SM-7351-RES-0402]
R162  0  [SM-7351-RES-0402]
R163  0  [SM-7351-RES-0402]
R164  0  [SM-7351-RES-0402]
R165  0  [SM-7351-RES-0402]
R166  0  [SM-7351-RES-0402]
R167  0  [SM-7351-RES-0402]
R168  0  [SM-7351-RES-0402]
R169  0  [SM-7351-RES-0402]
R170  0  [SM-7351-RES-0402]
R171  0  [SM-7351-RES-0402]
R172  0  [SM-7351-RES-0402]
R173  0  [SM-7351-RES-0402]
R174  0  [SM-7351-RES-0402]
R175  0  [SM-7351-RES-0402]
R176  0  [SM-7351-RES-0402]
R177  0  [SM-7351-RES-0402]
R179  0  [SM-7351-RES-0402]
R180  0  [SM-7351-RES-0603]
R181  0  [SM-7351-RES-0402]
R182  49.9  [SM-7351-RES-0402]
R183  49.9  [SM-7351-RES-0402]
R184  49.9  [SM-7351-RES-0402]
R185  49.9  [SM-7351-RES-0402]
R186  4.87K  [SM-7351-RES-0402]
R187  2.2K  [sm-7351-res-0402]
R188  0  [SM-7351-RES-0402]
R189  0  [SM-7351-RES-0402]
R190  10K  [SM-7351-RES-0402]
R191  2.2K  [sm-7351-res-0402]
R192  2.2K  [sm-7351-res-0402]
R193  2.2K  [sm-7351-res-0402]
R194  2.2K  [sm-7351-res-0402]
R195  0  [SM-7351-RES-0402]
R196  0  [SM-7351-RES-0402]
R197  0  [SM-7351-RES-0402]
R198  0  [SM-7351-RES-0402]
R199  0  [SM-7351-RES-0402]
U15  TLK105L  [qfn5x5-32-39m]
U70  SN74LVC1G08  [sm-so-sc70-5]
sheet Pg14: ICSS2 Ethernet 1
C140  0.1uF  [CC0402]
C141  0.1uF  [CC0402]
C142  10000pF  [CC0402]
C143  0.1uF  [CC0402]
C144  10000pF  [CC0402]
C145  0.1uF  [CC0402]
C146  4700pF  [CC0402]
C147  0.1uF  [CC0402]
C148  0.1uF  [CC0402]
C149  10uF  [CC0805]
C150  0.1uF  [CC0402]
C151  10000pF  [CC0402]
J4  HEADER 5  [HEADER_5X1]
J8  RJ-45 10_100Mb  [CNRJ45-1X1WLED]
R115  0  [SM-7351-RES-0402]
R117  0  [SM-7351-RES-0402]
R118  0  [SM-7351-RES-0402]
R119  0  [SM-7351-RES-0402]
R200  2.2K  [sm-7351-res-0402]
R201  2.2K  [sm-7351-res-0402]
R202  0  [SM-7351-RES-0402]
R203  0  [SM-7351-RES-0402]
R204  0  [SM-7351-RES-0402]
R205  0  [SM-7351-RES-0402]
R206  0  [SM-7351-RES-0402]
R207  0  [SM-7351-RES-0402]
R208  0  [SM-7351-RES-0402]
R209  0  [SM-7351-RES-0402]
R210  0  [SM-7351-RES-0402]
R211  0  [SM-7351-RES-0402]
R212  0  [SM-7351-RES-0402]
R213  0  [SM-7351-RES-0402]
R214  0  [SM-7351-RES-0402]
R215  0  [SM-7351-RES-0402]
R216  0  [SM-7351-RES-0402]
R217  0  [SM-7351-RES-0402]
R218  0  [SM-7351-RES-0603]
R219  0  [SM-7351-RES-0402]
R220  DNI  [SM-7351-RES-0402]
R221  0  [SM-7351-RES-0402]
R222  0  [SM-7351-RES-0603]
R223  0  [SM-7351-RES-0402]
R224  49.9  [SM-7351-RES-0402]
R225  49.9  [SM-7351-RES-0402]
R226  49.9  [SM-7351-RES-0402]
R227  49.9  [SM-7351-RES-0402]
R228  4.87K  [SM-7351-RES-0402]
R230  0  [SM-7351-RES-0402]
R231  0  [SM-7351-RES-0402]
R232  2.2K  [sm-7351-res-0402]
R233  10K  [SM-7351-RES-0402]
R234  0  [SM-7351-RES-0402]
R235  2.2K  [sm-7351-res-0402]
R236  2.2K  [sm-7351-res-0402]
R237  2.2K  [sm-7351-res-0402]
R238  2.2K  [sm-7351-res-0402]
R957  0  [SM-7351-RES-0402]
R958  DNI  [SM-7351-RES-0402]
U17  TLK105L  [qfn5x5-32-39m]
U71  SN74LVC1G08  [sm-so-sc70-5]
sheet Pg17: Gbit Ethernet #0
C153  0.1uF  [CC0402]
C154  10uF  [CC0805]
C155  0.1uF  [CC0402]
C156  10uF  [CC0805]
C157  47uF  [CC1206]
C158  47uF  [CC1206]
C159  10uF  [CC0805]
C160  0.1uF  [CC0402]
C161  10uF  [CC0805]
C162  0.1uF  [CC0402]
C163  10uF  [CC0805]
C164  0.1uF  [CC0402]
C165  10000pF  [CC0402]
C166  0.1uF  [CC0402]
C167  0.1uF  [CC0402]
C168  10uF  [CC0805]
C169  10000pF  [CC0402]
C170  10000pF  [CC0402]
C171  10000pF  [CC0402]
C172  18pF  [CC0402]
C173  18pF  [CC0402]
D3  MMSD103T1  [sod-123]
FB1  10 OHM  [FB0603]
FB2  10 OHM  [FB0603]
FB3  10 OHM  [FB0603]
FB4  10 OHM  [FB0603]
J10  RJ-45 Gigabit  [CNRJ45-1X1WLED-598M]
Q7  NTF6P02T3G  [SOT223]
R278  0  [SM-7351-RES-0603]
R279  1.5K OHM  [RC0402]
R280  100K  [SM-7351-RES-0402]
R281  22.1  [SM-7351-RES-0402]
R282  22.1  [SM-7351-RES-0402]
R283  22.1  [SM-7351-RES-0402]
R284  22.1  [SM-7351-RES-0402]
R285  22.1  [SM-7351-RES-0402]
R286  22.1  [SM-7351-RES-0402]
R287  22.1  [SM-7351-RES-0402]
R288  22.1  [SM-7351-RES-0402]
R289  22.1  [SM-7351-RES-0402]
R290  22.1  [SM-7351-RES-0402]
R291  22.1  [SM-7351-RES-0402]
R292  22.1  [SM-7351-RES-0402]
R293  220  [SM-7351-RES-0402]
R294  0  [SM-7351-RES-0402]
R295  0  [SM-7351-RES-0402]
R296  220  [SM-7351-RES-0402]
R297  4.7K  [SM-7351-RES-0402]
R298  12.1K  [SM-7351-RES-0402]
R299  10K  [SM-7351-RES-0402]
R301  10K  [SM-7351-RES-0402]
R304  1K  [SM-7351-RES-0402]
R305  1M  [SM-7351-RES-0402]
R306  10K  [SM-7351-RES-0402]
R308  0  [SM-7351-RES-0402]
R309  10K  [SM-7351-RES-0402]
R310  33  [SM-7351-RES-0402]
R312  0  [SM-7351-RES-0402]
R313  33  [SM-7351-RES-0402]
R314  0  [SM-7351-RES-0402]
R315  33  [SM-7351-RES-0402]
R317  1K  [SM-7351-RES-0402]
R319  1K  [SM-7351-RES-0402]
R321  1K  [SM-7351-RES-0402]
TP16  TP1mm  [tp_smd1mmcircle]
U21  KSZ9031RN  [qfn7x7-48]
U22  SN74LVC1G07  [u_5_dck]
U23  CDCE913  [TSSOP5X4-14-47M]
Y3  25MHz  [SM_OSC_ABM3]
sheet Pg18: Gbit Ethernet #1
C174  0.1uF  [CC0402]
C175  10uF  [CC0805]
C176  0.1uF  [CC0402]
C177  10uF  [CC0805]
C178  47uF  [CC1206]
C179  47uF  [CC1206]
C180  10uF  [CC0805]
C181  0.1uF  [CC0402]
C182  10uF  [CC0805]
C183  0.1uF  [CC0402]
C184  10uF  [CC0805]
C185  0.1uF  [CC0402]
C186  10000pF  [CC0402]
C187  0.1uF  [CC0402]
C188  0.1uF  [CC0402]
C189  10uF  [CC0805]
C190  10000pF  [CC0402]
C191  10000pF  [CC0402]
C192  10000pF  [CC0402]
C193  18pF  [CC0402]
C194  18pF  [CC0402]
D4  MMSD103T1  [sod-123]
FB5  10 OHM  [FB0603]
FB6  10 OHM  [FB0603]
FB7  10 OHM  [FB0603]
FB8  10 OHM  [FB0603]
J12  RJ-45 Gigabit  [CNRJ45-1X1WLED-598M]
Q8  NTF6P02T3G  [SOT223]
R322  0  [SM-7351-RES-0603]
R324  100K  [SM-7351-RES-0402]
R325  22.1  [SM-7351-RES-0402]
R326  22.1  [SM-7351-RES-0402]
R327  22.1  [SM-7351-RES-0402]
R328  22.1  [SM-7351-RES-0402]
R329  22.1  [SM-7351-RES-0402]
R330  22.1  [SM-7351-RES-0402]
R331  22.1  [SM-7351-RES-0402]
R332  22.1  [SM-7351-RES-0402]
R333  22.1  [SM-7351-RES-0402]
R334  22.1  [SM-7351-RES-0402]
R335  22.1  [SM-7351-RES-0402]
R336  22.1  [SM-7351-RES-0402]
R337  220  [SM-7351-RES-0402]
R338  0  [SM-7351-RES-0402]
R339  0  [SM-7351-RES-0402]
R340  220  [SM-7351-RES-0402]
R341  12.1K  [SM-7351-RES-0402]
R342  4.7K  [SM-7351-RES-0402]
R343  10K  [SM-7351-RES-0402]
R345  10K  [SM-7351-RES-0402]
R348  1K  [SM-7351-RES-0402]
R349  1M  [SM-7351-RES-0402]
R351  0  [SM-7351-RES-0402]
R352  10K  [SM-7351-RES-0402]
R353  10K  [SM-7351-RES-0402]
R354  33  [SM-7351-RES-0402]
R356  DNI  [SM-7351-RES-0402]
R357  33  [SM-7351-RES-0402]
R358  DNI  [SM-7351-RES-0402]
R359  33  [SM-7351-RES-0402]
R361  1K  [SM-7351-RES-0402]
R363  1K  [SM-7351-RES-0402]
R364  10K  [SM-7351-RES-0402]
TP17  TP1mm  [tp_smd1mmcircle]
U24  KSZ9031RN  [qfn7x7-48]
U25  CDCE913  [TSSOP5X4-14-47M]
U26  SN74LVC1G07  [u_5_dck]
Y4  25MHz  [SM_OSC_ABM3]
sheet Pg19: SDMMC #1 Interface
C211  0.1uF  [CC0402]
C212  4.7uF  [SM-7351-CAP-0603]
J15  503182-1852_CUS  [MOLEX_5031821852]
J44  DNI  [header_2x1]
R397  10K  [SM-7351-RES-0402]
R398  10K  [SM-7351-RES-0402]
R399  10K  [SM-7351-RES-0402]
R400  10K  [SM-7351-RES-0402]
R401  10K  [SM-7351-RES-0402]
R402  0  [SM-7351-RES-0402]
R403  0  [SM-7351-RES-0402]
R404  0  [SM-7351-RES-0402]
R405  0  [SM-7351-RES-0402]
R406  0  [SM-7351-RES-0402]
R407  0  [SM-7351-RES-0402]
R408  470K  [SM-7351-RES-0402]
R409  0  [SM-7351-RES-0402]
R644  10K  [SM-7351-RES-0402]
U30  TPD6E001  [U_10_RSE]
U84  TPD1E10B06  [tpd1e10b06-2l]
sheet Pg22: HDMI
U1  AM5729BABCXEA  [BGA23X23-760-117M]  (sections -1,-10,-11,-12,-13,-14,-15,-16,-17,-18,-19,-2,-20,-21,-22,-23,-24,-25,-26,-27,-28,-29,-3,-4,-5,-6,-7,-8,-9)
sheet Pg32: RTC & VPP Circuit
C1_1  1uF  [CC0603]
C2_1  1uF  [CC0603]
C246  15pF  [CC0402]
C247  15pF  [CC0402]
C248  10000pF  [CC0402]
J1_1  Receptacle 4x1  [HDR4X1RA-108M]
R1_1  0  [SM-7351-RES-0603]
R2_1  10K  [SM-7351-RES-0402]
R497  0  [SM-7351-RES-0402]
R498  DNI  [SM-7351-RES-0402]
R499  0  [SM-7351-RES-0402]
R500  DNI  [SM-7351-RES-0402]
R643  0  [SM-7351-RES-0402]
R645  10K  [SM-7351-RES-0402]
R923  0  [SM-7351-RES-0402]
R924  0  [SM-7351-RES-0402]
R925  0  [SM-7351-RES-0402]
R926  0  [SM-7351-RES-0402]
R927  DNI  [SM-7351-RES-0402]
R928  DNI  [SM-7351-RES-0402]
R929  DNI  [SM-7351-RES-0402]
TP1_1  TP  [TH_TP_5002]
TP19  TP1mm  [tp_smd1mmcircle]
U1_1  TLV70718  [X2SON1X1-4-16M]
U39  DNI SN74LVC1G07  [u_5_dck]
Y6  32.768KHz MC-306  [MC-306]

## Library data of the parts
C1 C2 = 04025A180JAT2A
C3 C28 C130 C137 C139 C142 C144 C151 C165 C169-C171 C186 C190-C192 C214 C248 C267 C327-C332 C334-C339 C341-C346 C348 C349 C351-C353 C355-C360 C362-C365 C367-C374 C376-C381 C385 C386 C388 C389 C391 C394 C422 C423 C485-C487 C564 C567 C569 C571-C577 = CC0402KRX7R7BB103
C4 C5 C442 C445-C447 C565 C568 = CGB2A1X5R1E105K033BC
C128 C129 C132-C135 C138 C140 C141 C143 C145 C147 C148 C150 C153 C155 C160 C162 C164 C174 C176 C181 C183 C185 C211 C213 C390 C393 C563 C566 = CC0402JRX7R7BB104
C570 = C0402C104J4RACTU
R2 R10 R22 R190 R233 R299 R301 R306 R309 R343 R345 R352 R353 R364 R397-R401 R498 R644 R645 R799 R914 R917 = RMCF0402FT10K0
R4 R305 R349 = 1MOhmResistor1_16W0402: Resistor 1Mohm 1/16W 1% 0402; MANUFACTURER: STACKPOLE ELECTRONICS
R5-R9 R13 R23-R31 R115 R117-R119 R160-R177 R179 R181 R188 R189 R195-R199 R202-R217 R219-R221 R223 R230 R231 R234 R294 R295 R308 R312 R314 R338 R339 R351 R356 R358 R402-R407 R409 R497 R499 R500 R569 R643 R915 R918-R927 R957 = 1R_ZeroOhmResistor1_16W0402: Resistor Zero ohm Jumper 0402; MANUFACTURER: PANASONIC
R11 R916 = 1R_100ohm1_16W1%SMD0402: Resistor 100ohm 1/10W 1% 0402; Cost100: 0.02; MANUFACTURER: PANASONIC; MfrNum: ERJ-2RKF1000X; PartName: 100ohm1/10W1%0402; TIIntPartnumber: 1R0246
R36 R929 = 1R_18.2Kohm1_16W1%smd0402: Resistor 18.2Kohm 1/16W 1% 0402; MANUFACTURER: Vishay Dale
R793 R928 = 1R_20.5Kohm1_16W1%smd0402: Resistor 20.5Kohm 1/16W 1% 0402; MANUFACTURER: PANASONIC
SW1 SW2 = 2W_Switch_Pushbuttonsmd: Switch Push Button tactile NO; MANUFACTURER: Omron
U2 U22 U26 U39 U47 U97 = SN74LVC1G07DCKRE4: MANUFACTURER: TEXAS INSTRUMENT
U48 U49 U84 = TPD1E10B06DPYR: TVS DIODE 5.5V 14V 2X1SON; MANUFACTURER: TI
U70 U71 U98 = SN74LVC1G08DCKR: MANUFACTURER: TI
Y1 = ABM7-20.000MHZ-D2Y-T
C136 C149 C154 C156 C159 C161 C163 C168 C175 C177 C180 C182 C184 C189 C266 C333 C340 C347 C354 C361 C375 C384 C387 C395 C396 C413 C414 C483 = CL21A106KOQNNNG
C473-C475 = T491D476K010AT
L21 L24-L26 L34 L35 = 1L_NFM21PC474_EMIFilter_0: EMI/RF Suppression Filter; MANUFACTURER: Murata
U4 = 1A_S25FL256S_QSPI: Quad Serial NOR Flash Memory 256Mb 3.3V; MANUFACTURER: Spansion
C131 C146 = 04025C472KAT2A
J6 J8 = 2J_ConnectorRJ45_10_0: Connector MagRJ-45 Jack w/LED 10_100Mb - Auto MDIX; MANUFACTURER: Link
J4 J7 = 2H_Header_5x1: Single Line Header 5pin Tin 0.1in pitch; MANUFACTURER: Sullins
R159 R187 R191-R194 R200 R201 R232 R235-R238 = 1R_2.2KOhmResistor1_16W0402: MANUFACTURER: VishayDale
R180 R218 R222 R278 R322 = 1R_ZeroOhmResistor1_16W0603: Resistor Zero ohm Jumper 0603; MANUFACTURER: PANASONIC
R182-R185 R224-R227 R958 = 1R_49.9OhmResistor1_16W0402: Resistor 49.9ohm 1/16W 1% 0402; MANUFACTURER: PANASONIC
R186 R228 = 1R_4.87Kohm1_16W1%smd0402: Resistor 4.87Kohm 1/16W 1% 0402; MANUFACTURER: STACKPOLE ELECTRONICS
U15 U17 = TLK105LRHBR: MANUFACTURER: TEXAS INSTRUMENTS
C157 C158 C178 C179 = CL31A476MPHNNNE
C166 C167 C187 C188 = CGA2B3X7R1H104K050BE
C172 C173 C193 C194 = CL05C180JB5NNNC
D3 D4 = Diode200mA250V_0: Diode 200mA 250V 1.25V Forward Drop; MANUFACTURER: On Semiconductor; TIIntPartnumber: _1E0013
FB1-FB8 = BLM18BB100SN1D
J10 J12 = 2J_ConnectorRJ45_Gigabit
Q7 Q8 = NTF6P02T3G
R279 = RC0402JR-071K5L
R280 R324 = 1R_100KOhmResistor1_16W0402: Resistor 100Kohm 1/16W 1% 0402; MANUFACTURER: STACKPOLE ELECTRONICS
R281-R292 R325-R336 = RMCF0402FT22R1
R293 R296 R337 R340 = 1R_220ohm1_10W1%smd0402: Resistor 220ohm 1/10W 1% 0402; MANUFACTURER: PANASONIC
R297 R342 = 1R_4.7KOhmResistor1_16W0402: Resistor 4.7Kohm 1/16W 5% 0402; MANUFACTURER: STACKPOLE ELECTRONICS
R298 R341 = 1R_12.1KohmResistor1_16W1%0402: Resistor 12.1K OHM 1/16W 1% 0402 SMD; MANUFACTURER: Yageo
R304 R317 R319 R321 R348 R361 R363 = 1R_1KOhmResistor1_16W0402: Resistor 1Kohm 1/16W 5% 0402; MANUFACTURER: PANASONIC
R310 R313 R315 R354 R357 R359 = 1R_33ohmResistor1_16W5%0402: Resistor 33ohm 1/16W 5% 0402; MANUFACTURER: PANASONIC
TP16 TP17 TP19 = 2H_Testpoint_SMD1mmCircle: Testpoint SMD 1mm circle pad; MANUFACTURER: N/A
U21 U24 = KSZ9031RNXCC: MANUFACTURER: MICROCHIP
U23 U25 = 1A_CDCE913: Programmable 1-PLL VCXO Clock Synthesizer; MANUFACTURER: TI
Y3 Y4 = 1Y_Crystal25MHzABM3_0: Crystal 25MHz; MANUFACTURER: Abracon
C212 = 1C_4.7uFCapacitor16V10%0603: Capacitor Ceramic 4.7uF 16V 10% 0603; MANUFACTURER: Taiyo Yuden
J15 = 503182-1852_CUS
J44 = 2H_Header_0: Single Line Header 2pin Tin 0.1in pitch; MANUFACTURER: OnShoreTechnology
R408 = 470Kohm1_16W1%SMD0402: MANUFACTURER: STACKPOLE ELECTRONICS
U30 = TPD6E001RSER: MANUFACTURER: TEXAS INSTRUMENTNS
U1 = AM5729BABCXEA
C1_1 C2_1 = CL10A105KB8NNNC
C246 C247 = CC0402JRNPO9BN150
J1_1 = 2H_Header_4x1_female: Header female 4pin 0.1in pitch right angle; DNI: DNI; MANUFACTURER: Sullins
R1_1 = 1R_ZeroOhmResistor1_16W0603: Resistor Zero ohm Jumper 0603; DNI: DNI; MANUFACTURER: PANASONIC
R2_1 = RMCF0402FT10K0: DNI: DNI
TP1_1 = 2H_TestPointThroughHole: Testpoint Miniature Through Hole; DNI: DNI; MANUFACTURER: Keystone Electronics
U1_1 = 1A_TLV70717: Linear Regulator LDO 3.3V 350mA ultralow Vin; DNI: DNI; MANUFACTURER: TI; MfrNum: TLV70718DQN
Y6 = MC-306_32.7680K-A0: MANUFACTURER: Epson

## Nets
AGND_GBETH0: C166.2 C167.2 J10.SHLD1 J10.SHLD2
AGND_GBETH1: C187.2 C188.2 J12.SHLD1 J12.SHLD2
AGNDFRAME_PRU2ETH0: C131.2 J6.SHLD1 J6.SHLD2
AGNDFRAME_PRU2ETH1: C146.2 J8.SHLD1 J8.SHLD2
DGND: C1_1.2 C2_1.2 C3.2 C4.2 C5.2 C28.2 C128.2 C129.2 C130.2 C131.1 C132.2 C133.2 C134.2 C135.2 C136.2 C137.2 C138.2 C139.2 C140.2 C141.2 C142.2 C143.2 C144.2 C145.2 C146.1 C147.2 C148.2 C149.2 C150.2 C151.2 C153.2 C154.2 C155.2 C156.2 C157.2 C158.2 C159.2 C160.2 C161.2 C162.2 C163.2 C164.2 C165.2 C166.1 C167.1 C168.2 C169.2 C170.2 C171.2 C172.1 C173.1 C174.2 C175.2 C176.2 C177.2 C178.2 C179.2 C180.2 C181.2 C182.2 C183.2 C184.2 C185.2 C186.2 C187.1 C188.1 C189.2 C190.2 C191.2 C192.2 C193.1 C194.1 C211.2 C212.2 C213.2 C214.2 C246.2 C247.2 C248.2 C266.2 C267.2 C327.2 C328.2 C329.2 C330.2 C331.2 C332.2 C333.2 C334.2 C335.2 C336.2 C337.2 C338.2 C339.2 C340.2 C341.2 C342.2 C343.2 C344.2 C345.2 C346.2 C347.2 C348.2 C349.2 C351.2 C352.2 C353.2 C354.2 C355.2 C356.2 C357.2 C358.2 C359.2 C360.2 C361.2 C362.2 C363.2 C364.2 C365.2 C367.2 C368.2 C369.2 C370.2 C371.2 C372.2 C373.2 C374.2 C375.2 C376.2 C377.2 C378.2 C379.2 C380.2 C381.2 C384.2 C385.2 C386.2 C387.2 C388.2 C389.2 C390.2 C391.2 C393.2 C394.2 C395.2 C396.2 C413.2 C414.2 C422.2 C423.2 C442.2 C445.2 C446.2 C447.2 C473.2 C474.2 C475.2 C483.2 C485.2 C486.2 C487.2 C563.2 C564.2 C565.2 C566.2 C567.2 C568.2 C569.2 C570.2 C571.2 C572.2 C573.2 C574.2 C575.2 C576.2 C577.2 J1_1.1 J4.5 J6.8 J7.5 J8.8 J10.1 J10.12 J10.13 J12.1 J12.12 J12.13 J15.6(VSS) J15.G1 J15.G2 J15.G3 J15.G4 J15.G5 J15.SW J44.2 L21.2(GND) L24.2(GND) L25.2(GND) L26.2(GND) L34.2(GND) L35.2(GND) R2_1.2 R13.2(P2) R172.2(P2) R186.1(P1) R187.1(P1) R191.1(P1) R192.1(P1) R193.1(P1) R194.1(P1) R228.1(P1) R235.1(P1) R236.1(P1) R237.1(P1) R238.1(P1) R298.2 R304.1(P1) R317.1(P1) R319.1(P1) R321.1(P1) R341.2 R348.1(P1) R361.1(P1) R363.1(P1) R569.2(P2) R643.2(P2) R793.1(P1) R923.2(P2) R924.2(P2) R925.2(P2) R927.1(P1) R928.1(P1) SW1.1 SW1.2 SW2.1 SW2.2 TP1_1.1 U1.AC14(VSSA_OSC1) U1_1.2(GND) U1_1.TPAD U2.3(GND) U4.10(VSS) U15.TPAD U17.TPAD U21.13(VSS_PS) U21.29(VSS) U21.49(P_GND) U22.3(GND) U23.5(GND1) U23.10(GND2) U24.13(VSS_PS) U24.29(VSS) U24.49(P_GND) U25.5(GND1) U25.10(GND2) U26.3(GND) U30.5(GND) U39.3(GND) U47.3(GND) U48.2 U49.2 U70.3(GND) U71.3(GND) U84.2 U97.3(GND) U98.3(GND) ; also on sheet 1 2 3 4 5 6 8 9 11 12 13 14 15 16 17 18 19 20 21 22 23 24 34 35
GND_OSC0: C1.2 C2.2 R13.1(P1) U1.AF15(VSSA_OSC0)
V1_8D: C1_1.1 C169.1 C190.1 C368.1 C372.1 C373.1 C374.1 C375.1 C376.1 C377.1 C378.1 C379.1 R1_1.2(P2) U1_1.1(OUT) U23.3(VDD) U25.3(VDD) ; also on sheet 5 19 22
V1_8D_OUT: J1_1.2 R1_1.1(P1)
V1_8PHY_HDMI: C566.1 C567.1 C568.1 L35.3(OUT) ; also on sheet 22
V1_8PHY_LDO3: L25.1(IN) L34.1(IN) ; also on sheet 19
V1_8PHY_LDO4: L26.1(IN) L35.1(IN) ; also on sheet 19
V1_8PHY_PCIE: C393.1 C394.1 C447.1 L26.3(OUT) ; also on sheet 22
V1_8PHY_SATA: C563.1 C564.1 C565.1 L34.3(OUT) ; also on sheet 22
V1_8PHY_USB: C390.1 C391.1 C446.1 L25.3(OUT) ; also on sheet 22
V1_8PLL: L21.1(IN) L24.1(IN) ; also on sheet 19 22
V1_8PLLA: C380.1 C381.1 C442.1 L21.3(OUT) ; also on sheet 22
V1_8PLLB: C388.1 C389.1 C445.1 L24.3(OUT) ; also on sheet 22
V3_3D: C2_1.1 C3.1 C28.1 C130.1 C132.1 C133.1 C139.1 C143.1 C144.1 C145.1 C151.1 C170.1 C191.1 C211.1 C212.1 C214.1 C248.1 C360.1 C361.1 C362.1 C363.1 C364.1 C365.1 C367.1 C384.1 C385.1 C386.1 C569.1 C571.1 FB1.1 FB5.1 J1_1.3 J15.4(VDD) R2.2 R8.2(P2) R10.2 R22.2 R159.2(P2) R160.2(P2) R161.2(P2) R180.1(P1) R182.1(P1) R183.1(P1) R184.1(P1) R185.1(P1) R190.2 R200.2(P2) R201.2(P2) R202.2(P2) R203.2(P2) R214.2(P2) R222.1(P1) R224.1(P1) R225.1(P1) R226.1(P1) R227.1(P1) R232.2(P2) R233.2 R278.2(P2) R322.2(P2) R498.2 R799.2 R914.2 R917.2 R958.2(P2) U1_1.4(IN) U2.5(VCC) U4.2(VCC) U4.14(VIO/RFU) U15.21(VDD33_IO) U17.21(VDD33_IO) U23.6(VDDOUT1) U23.7(VDDOUT2) U25.6(VDDOUT1) U25.7(VDDOUT2) U30.10(VCC) U39.2(A) U39.5(VCC) U47.5(VCC) U70.5(VCC) U71.5(VCC) U97.5(VCC) U98.5(VCC) ; also on sheet 2 3 4 5 6 8 9 11 12 13 14 15 16 17 18 19 21 22 23 24 34 35
V3_3D_PRU2ETH0JCK: C128.1 C129.1 J6.3 J6.4 R160.1(P1)
V3_3D_PRU2ETH1JCK: C140.1 C141.1 J8.3 J8.4 R202.1(P1)
VDD_CORE: C339.1 C340.1 C341.1 C342.1 C343.1 C344.1 C345.1 C387.1 C473.1 C572.1 C573.1 C574.1 C575.1 C576.1 C577.1 ; also on sheet 21 22
VDD_DSPEVE: C353.1 C354.1 C355.1 C356.1 C357.1 C358.1 C359.1 C414.1 C422.1 C423.1 C475.1 ; also on sheet 21 22
VDD_GPU: C266.1 C267.1 C327.1 C328.1 C329.1 C330.1 C331.1 C396.1 ; also on sheet 21 22
VDD_IVA: C346.1 C347.1 C348.1 C349.1 C351.1 C413.1 ; also on sheet 21 22
VDD_MPU: C332.1 C333.1 C334.1 C335.1 C336.1 C337.1 C338.1 C352.1 C369.1 C370.1 C371.1 C395.1 C474.1 ; also on sheet 21 22
AM57XX_MMC1_CLK: R405.2(P2) U1.W6(MMC1_CLK)
AM57XX_MMC1_CMD: R404.2(P2) U1.Y6(MMC1_CMD)
AM57XX_MMC1_DAT0: R406.2(P2) U1.AA6(MMC1_DAT0)
AM57XX_MMC1_DAT1: R407.2(P2) U1.Y4(MMC1_DAT1)
AM57XX_MMC1_DAT2: R402.2(P2) U1.AA5(MMC1_DAT2)
AM57XX_MMC1_DAT3: R403.2(P2) U1.Y3(MMC1_DAT3)
AM57XX_MMC1_SDCD: R409.2(P2) U1.W7(MMC1_SDCD)
AM57XX_MMC1_SDWP: J44.1 R644.1 U1.Y9(MMC1_SDWP)
AM57XX_OSC0_IN: C2.1 R4.2(P2) U1.AE15(XI_OSC0) Y1.2
AM57XX_OSC0_OUT: R5.1(P1) U1.AD15(XO_OSC0)
AM57XX_PORZn: R6.1(P1) U1.F22(PORZ)
AM57XX_PR1_UART0_TXD: R199.2(P2) ; also on sheet 12 34
AM57XX_PRU1ETH1_MRCLK: R332.2 U1.C3(VIN2A_D14/RGMII1_TXD3) ; also on sheet 17
AM57XX_PRU1ETH1_TXD0: R326.2 U1.C2(VIN2A_D13/RGMII1_TXCTL) ; also on sheet 17
AM57XX_PRU1ETH1_TXD1: R325.2 U1.D5(VIN2A_D12/RGMII1_TXC) ; also on sheet 17
AM57XX_PRU2ETH0_COL: U1.F15(MCASP3_FSX/PR2_MII0_COL) ; also on sheet 34
AM57XX_PRU2ETH0_CRS: R177.2(P2) U1.B18(MCASP3_ACLKX/PR2_MII0_CRS) ; also on sheet 34
AM57XX_PRU2ETH0_MRCLK: R165.2(P2) U1.A13(MCASP1_AXR13/PR2_MII_MR0_CLK)
AM57XX_PRU2ETH0_RXD0: R171.2(P2) U1.C15(MCASP2_AXR2/PR2_MII0_RXD0)
AM57XX_PRU2ETH0_RXD1: R173.2(P2) U1.A18(MCASP2_FSX/PR2_MII0_RXD1)
AM57XX_PRU2ETH0_RXD2: R174.2(P2) U1.A19(MCASP2_ACLKX/PR2_MII0_RXD2)
AM57XX_PRU2ETH0_RXD3: R175.2(P2) U1.F14(MCASP1_AXR15/PR2_MII0_RXD3)
AM57XX_PRU2ETH0_RXDV: R166.2(P2) R197.2(P2) U1.G14(MCASP1_AXR14/PR2_MII0_RXDV)
AM57XX_PRU2ETH0_RXER: R170.2(P2) U1.G12(MCASP1_AXR0/PR2_MII0_RXER)
AM57XX_PRU2ETH0_RXLINK: R188.2(P2) U1.A16(MCASP2_AXR3/PR2_MII0_RXLINK)
AM57XX_PRU2ETH0_TXCLK: R162.2(P2) U1.F12(MCASP1_AXR1/PR2_MII_MT0_CLK)
AM57XX_PRU2ETH0_TXD0: R163.2(P2) U1.E14(MCASP1_AXR12/PR2_MII0_TXD0)
AM57XX_PRU2ETH0_TXD1: R164.2(P2) U1.A12(MCASP1_AXR11/PR2_MII0_TXD1)
AM57XX_PRU2ETH0_TXD2: R168.2(P2) U1.B13(MCASP1_AXR10/PR2_MII0_TXD2)
AM57XX_PRU2ETH0_TXD3: R169.2(P2) U1.A11(MCASP1_AXR9/PR2_MII0_TXD3)
AM57XX_PRU2ETH0_TXEN: R167.2(P2) R196.2(P2) U1.B12(MCASP1_AXR8/PR2_MII0_TXEN)
AM57XX_PRU2ETH1_COL: R220.2(P2) U1.D18(XREF_CLK0/PR2_MII1_COL) ; also on sheet 34
AM57XX_PRU2ETH1_CRS: R219.2(P2) U1.E17(XREF_CLK1/PR2_MII1_CRS) ; also on sheet 34
AM57XX_PRU2ETH1_MRCLK: R209.2(P2) U1.AC9(MMC3_DAT2/PR2_MII_MR1_CLK)
AM57XX_PRU2ETH1_RXD0: R213.2(P2) U1.AB5(MMC3_DAT7/PR2_MII1_RXD0)
AM57XX_PRU2ETH1_RXD1: R215.2(P2) U1.AB8(MMC3_DAT6/PR2_MII1_RXD1)
AM57XX_PRU2ETH1_RXD2: R216.2(P2) U1.AD6(MMC3_DAT5/PR2_MII1_RXD2)
AM57XX_PRU2ETH1_RXD3: R217.2(P2) U1.AC8(MMC3_DAT4/PR2_MII1_RXD3)
AM57XX_PRU2ETH1_RXDV: R211.2(P2) U1.AC3(MMC3_DAT3/PR2_MII1_RXDV)
AM57XX_PRU2ETH1_RXER: R212.2(P2) U1.B19(MCASP3_AXR0/PR2_MII1_RXER)
AM57XX_PRU2ETH1_TXCLK: R204.2(P2) U1.AC5(GPIO6_10/PR2_MII_MT1_CLK)
AM57XX_PRU2ETH1_TXD0: R206.2(P2) U1.AC6(MMC3_DAT1/PR2_MII1_TXD0)
AM57XX_PRU2ETH1_TXD1: R208.2(P2) U1.AC7(MMC3_DAT0/PR2_MII1_TXD1)
AM57XX_PRU2ETH1_TXD2: R210.2(P2) U1.AC4(MMC3_CMD/PR2_MII1_TXD2)
AM57XX_PRU2ETH1_TXD3: R207.2(P2) U1.AD4(MMC3_CLK/PR2_MII1_TXD3)
AM57XX_PRU2ETH1_TXEN: R205.2(P2) U1.AB4(GPIO6_11/PR2_MII1_TXEN)
AM57XX_PRU2ETH_MDCLK: R179.2(P2) R221.2(P2) U1.C14(MCASP1_ACLKX/PR2_MDIO_MDCLK)
AM57XX_PRU2ETH_MDDATA: R181.2(P2) R223.2(P2) U1.D14(MCASP1_FSX/PR2_MDIO_DATA)
AM57XX_RGMII0_RD0: R289.2 U1.W2(RGMII0_RXD0) ; also on sheet 24
AM57XX_RGMII0_RD1: R290.2 U1.Y2(RGMII0_RXD1) ; also on sheet 24
AM57XX_RGMII0_RD2: R291.2 U1.V3(RGMII0_RXD2) ; also on sheet 24
AM57XX_RGMII0_RD3: R292.2 U1.V4(RGMII0_RXD3) ; also on sheet 24
AM57XX_RGMII0_RXCLK: R288.2 U1.U5(RGMII0_RXC) ; also on sheet 24
AM57XX_RGMII0_RXCTL: R285.2 U1.V5(RGMII0_RXCTL) ; also on sheet 24
AM57XX_RGMII0_TD0: R282.2 U1.U6(RGMII0_TXD0) ; also on sheet 24
AM57XX_RGMII0_TD1: R287.2 U1.V6(RGMII0_TXD1) ; also on sheet 24
AM57XX_RGMII0_TD2: R283.2 U1.U7(RGMII0_TXD2) ; also on sheet 24
AM57XX_RGMII0_TD3: R284.2 U1.V7(RGMII0_TXD3) ; also on sheet 24
AM57XX_RGMII0_TXCLK: R281.2 U1.W9(RGMII0_TXC) ; also on sheet 24
AM57XX_RGMII0_TXCTL: R286.2 U1.V9(RGMII0_TXCTL) ; also on sheet 24
AM57XX_RGMII1_RD0: R333.2 U1.A4(VIN2A_D23/RGMII1_RXD0) ; also on sheet 17
AM57XX_RGMII1_RD1: R334.2 U1.B5(VIN2A_D22/RGMII1_RXD1) ; also on sheet 17
AM57XX_RGMII1_RD2: R335.2 U1.B4(VIN2A_D21/RGMII1_RXD2) ; also on sheet 17
AM57XX_RGMII1_RD3: R336.2 U1.B3(VIN2A_D20/RGMII1_RXD3) ; also on sheet 17
AM57XX_RGMII1_RXCLK: R328.2 U1.C5(VIN2A_D18/RGMII1_RXC) ; also on sheet 17
AM57XX_RGMII1_RXCTL: R329.2 U1.A3(VIN2A_D19/RGMII1_RXCTL) ; also on sheet 17
AM57XX_RGMII1_TD0: R330.2 U1.D6(VIN2A_D17/RGMII1_TXD0) ; also on sheet 17
AM57XX_RGMII1_TD1: R331.2 U1.B2(VIN2A_D16/RGMII1_TXD1) ; also on sheet 17
AM57XX_RGMII1_TD2: R327.2 U1.C4(VIN2A_D15/RGMII1_TXD2) ; also on sheet 17
AM57XX_RSTOUTn: R36.2(P2) R922.2(P2) U1.F23(RSTOUTn) U47.2(A)
AM57XX_VIN2A_DE0: R119.2(P2) ; also on sheet 34
AM57XX_VIN2A_HSYNC0: R118.2(P2) ; also on sheet 34
AM57XX_VIN2A_VSYNC0: R198.2(P2) ; also on sheet 34
AM574X_HDMI_DDC_SCL: R358.2(P2) ; also on sheet 4
AM574X_HDMI_DDC_SDA: R356.2(P2) ; also on sheet 4
AM574X_QSPI_CLK: R24.2(P2) U1.R2(GPMC_A18/QSPI1_SCLK)
AM574X_QSPI_CSn: R30.2(P2) U1.P2(GPMC_CS2/QSPI1_CS0)
AM574X_QSPI_D0: R25.2(P2) U1.U1(GPMC_A16/QSPI1_D0)
AM574X_QSPI_D1: R26.2(P2) U1.P3(GPMC_A17/QSPI1_D1)
AM574X_QSPI_D2: R27.2(P2) U1.U2(GPMC_A15/QSPI_D2)
AM574X_QSPI_D3: R28.2(P2) U1.T2(GPMC_A14/QSPI_D3)
AM574X_QSPI_RTCLK: R23.2(P2) U1.R3(GPMC_A13/QSPI_RTCLK)
ETH0_LDO_O: Q7.1(G) U21.43(LDO_O)
ETH0_MDC: R294.1(P1) U21.36(MDC)
ETH0_MDIO: R295.1(P1) U21.37(MDIO)
ETH0_RXCLK: R288.1 R317.2(P2) U21.35(RX_CLK)
ETH0_RXD0: R289.1 R299.2 U21.32(RXD0)
ETH0_RXD1: R290.1 R301.2 U21.31(RXD1)
ETH0_RXD2: R291.1 R306.2 U21.28(RXD2)
ETH0_RXD3: R292.1 R309.2 U21.27(RXD3)
ETH0_RXDV: R285.1 R304.2(P2) U21.33(RX_DV)
ETH0_TXCLK: R281.1 U21.24(GTX_CLK)
ETH0_TXD0: R282.1 U21.19(TXD0)
ETH0_TXD1: R287.1 U21.20(TXD1)
ETH0_TXD2: R283.1 U21.21(TXD2)
ETH0_TXD3: R284.1 U21.22(TXD3)
ETH0_TXEN: R286.1 U21.25(TX_EN)
ETH0GB_25MHzCLK: R315.2 U21.46(XI)
ETH1_LDO_O: Q8.1(G) U24.43(LDO_O)
ETH1_MDC: R338.1(P1) U24.36(MDC)
ETH1_MDIO: R339.1(P1) U24.37(MDIO)
ETH1_RESETn: C189.1 D4.2(Anode) R324.1(P1) U24.42(RESET_N) U26.4(Y)
ETH1_RXCLK: R328.1 R361.2(P2) U24.35(RX_CLK)
ETH1_RXD0: R333.1 R343.2 U24.32(RXD0)
ETH1_RXD1: R334.1 R345.2 U24.31(RXD1)
ETH1_RXD2: R335.1 R352.2 U24.28(RXD2)
ETH1_RXD3: R336.1 R353.2 U24.27(RXD3)
ETH1_RXDV: R329.1 R348.2(P2) U24.33(RX_DV)
ETH1_TXCLK: R325.1 U24.24(GTX_CLK)
ETH1_TXD0: R330.1 U24.19(TXD0)
ETH1_TXD1: R331.1 U24.20(TXD1)
ETH1_TXD2: R327.1 U24.21(TXD2)
ETH1_TXD3: R332.1 U24.22(TXD3)
ETH1_TXEN: R326.1 U24.25(TX_EN)
ETH1GB_25MHzCLK: R359.2 U24.46(XI)
ETH_MDIO_CLK: R294.2(P2) R338.2(P2) U1.V1(MDIO_MCLK) ; also on sheet 24
ETH_MDIO_DATA: R279.1 R295.2(P2) R339.2(P2) U1.U4(MDIO_D) ; also on sheet 24
ETHER0_D0N: J10.10 U21.3(TXRXM_A)
ETHER0_D0P: J10.9 U21.2(TXRXP_A)
ETHER0_D1N: J10.8 U21.6(TXRXM_B)
ETHER0_D1P: J10.7 U21.5(TXRXP_B)
ETHER0_D2N: J10.6 U21.8(TXRXM_C)
ETHER0_D2P: J10.5 U21.7(TXRXP_C)
ETHER0_D3N: J10.4 U21.11(TXRXM_D)
ETHER0_D3P: J10.3 U21.10(TXRXP_D)
ETHER1_D0N: J12.10 U24.3(TXRXM_A)
ETHER1_D0P: J12.9 U24.2(TXRXP_A)
ETHER1_D1N: J12.8 U24.6(TXRXM_B)
ETHER1_D1P: J12.7 U24.5(TXRXP_B)
ETHER1_D2N: J12.6 U24.8(TXRXM_C)
ETHER1_D2P: J12.5 U24.7(TXRXP_C)
ETHER1_D3N: J12.4 U24.11(TXRXM_D)
ETHER1_D3P: J12.3 U24.10(TXRXP_D)
GB_ETH0_INTn: R297.1(P1) U21.38(INT_N_/_PME_N2) ; also on sheet 34
GB_ETH1_INTn: R342.1(P1) U24.38(INT_N_/_PME_N2) ; also on sheet 34
GBETH0_RESETn: C168.1 D3.2(Anode) R280.1(P1) U21.42(RESET_N) U22.4(Y)
GPIO_PRU2_ETH0_RESETn: R195.2(P2) ; also on sheet 34
GPIO_PRU2_ETH1_RESETn: R234.2(P2) ; also on sheet 34
IND_I2C_SCL: R314.2(P2) ; also on sheet 5 13 15 18 19 23 34
IND_I2C_SDA: R312.2(P2) ; also on sheet 5 13 15 18 19 23 34
MMC_CD: J15.DT R408.1(P1) R409.1(P1) U84.1
MMC_CLK: J15.5(CLK) R405.1(P1) U30.1(IO1)
MMC_CMD: J15.3(CMD) R398.1 R404.1(P1) U30.7(IO5)
MMC_D0: J15.7(DAT0) R399.1 R406.1(P1) U30.2(IO2)
MMC_D1: J15.8(DAT1) R400.1 R407.1(P1) U30.3(IO3)
MMC_D2: J15.1(DATA2) R401.1 R402.1(P1) U30.6(IO4)
MMC_D3: J15.2(CD/DAT3) R397.1 R403.1(P1) U30.8(IO6)
OSC0_OUT: C1.1 R4.1(P1) R5.2(P2) Y1.1
PCIE_RESETn: R919.1(P1) R920.1(P1) ; also on sheet 23
PHY0_LED_ACTn: R293.1 R321.2(P2) U21.17(LED1_/_PME_N1)
PHY0_LED_LINKn: R296.1 R319.2(P2) U21.15(LED2)
PHY1_LED_ACTn: R337.1 R364.2 U24.17(LED1_/_PME_N1)
PHY1_LED_LINKn: R340.1 R363.2(P2) U24.15(LED2)
PHY_RESETn: R915.1(P1) R921.1(P1) U22.2(A) U26.2(A) U70.2(B) U71.2(B) ; also on sheet 17 24
PMIC_EN: R645.1 R928.2(P2) R929.1(P1) ; also on sheet 19
PMIC_RESET_OUTn: R9.1(P1) ; also on sheet 19
PORZn: C213.1 R6.2(P2) R499.1(P1) R920.2(P2) R921.2(P2) R926.1(P1) U98.4(Y)
PR1_EDIO_DATA_OUT1: J4.4 R119.1(P1)
PR1_EDIO_DATA_OUT3: J4.3 R118.1(P1)
PR1_EDIO_DATA_OUT4: J7.3 R198.1(P1)
PR1_EDIO_DATA_OUT6: J7.4 R199.1(P1)
PR2_MII0_RXDV: J7.2 R197.1(P1)
PR2_MII0_TXEN: J7.1 R196.1(P1)
PR2_MII1_RXDV: J4.2 R117.1(P1)
PR2_MII1_TXEN: J4.1 R115.1(P1)
PRU1ETH0_25MHzCLK: R310.2 ; also on sheet 24
PRU1ETH1_25MHzCLK: R313.2 ; also on sheet 17
PRU2ETH0_25MHzCLK: R354.2 U15.23(XI)
PRU2ETH0_COL: R187.2(P2) R188.1(P1) R189.2(P2) U15.29(COL)
PRU2ETH0_CRS: R177.1(P1) U15.27(CRS)
PRU2ETH0_INTn: U15.8(PWRDNn/INTn) ; also on sheet 34
PRU2ETH0_LINKLED: R159.1(P1) R176.2(P2) U15.17(LED_LINK)
PRU2ETH0_MDC: R179.1(P1) U15.20(MDC)
PRU2ETH0_MDIO: R181.1(P1) U15.19(MDIO)
PRU2ETH0_RESETn: U15.18(RESET_N) U70.4(Y)
PRU2ETH0_RXCLK: R165.1(P1) U15.25(RX_CLK)
PRU2ETH0_RXD0: R171.1(P1) R194.2(P2) U15.30(RXD_0)
PRU2ETH0_RXD1: R173.1(P1) R193.2(P2) U15.31(RXD_1)
PRU2ETH0_RXD2: R174.1(P1) R192.2(P2) U15.32(RXD_2)
PRU2ETH0_RXD3: R175.1(P1) R191.2(P2) U15.1(RXD_3)
PRU2ETH0_RXDV: R166.1(P1) U15.26(RX_DV)
PRU2ETH0_RXERR: R170.1(P1) U15.28(RX_ERR)
PRU2ETH0_TXCLK: R162.1(P1) U15.2(TX_CLK)
PRU2ETH0_TXD0: R163.1(P1) U15.4(TXD_0)
PRU2ETH0_TXD1: R164.1(P1) U15.5(TXD_1)
PRU2ETH0_TXD2: R168.1(P1) U15.6(TXD_2)
PRU2ETH0_TXD3: R169.1(P1) U15.7(TXD_3)
PRU2ETH0_TXEN: R167.1(P1) U15.3(TX_EN)
PRU2ETH1_25MHzCLK: R357.2 U17.23(XI)
PRU2ETH1_COL: R220.1(P1) R231.1(P1) R232.1(P1) U17.29(COL) ; also on sheet 34
PRU2ETH1_CRS: R219.1(P1) U17.27(CRS) ; also on sheet 34
PRU2ETH1_INTn: U17.8(PWRDNn/INTn) ; also on sheet 34
PRU2ETH1_LINKLED: R200.1(P1) R218.2(P2) U17.17(LED_LINK)
PRU2ETH1_MDC: R221.1(P1) U17.20(MDC)
PRU2ETH1_MDIO: R201.1(P1) R223.1(P1) U17.19(MDIO)
PRU2ETH1_RESETn: U17.18(RESET_N) U71.4(Y)
PRU2ETH1_RXCLK: R209.1(P1) U17.25(RX_CLK)
PRU2ETH1_RXD0: R213.1(P1) R238.2(P2) U17.30(RXD_0)
PRU2ETH1_RXD1: R215.1(P1) R237.2(P2) U17.31(RXD_1)
PRU2ETH1_RXD2: R216.1(P1) R236.2(P2) U17.32(RXD_2)
PRU2ETH1_RXD3: R217.1(P1) R235.2(P2) U17.1(RXD_3)
PRU2ETH1_RXDV: R117.2(P2) R211.1(P1) U17.26(RX_DV)
PRU2ETH1_RXERR: R212.1(P1) U17.28(RX_ERR)
PRU2ETH1_TXCLK: R204.1(P1) U17.2(TX_CLK)
PRU2ETH1_TXD0: R206.1(P1) U17.4(TXD_0)
PRU2ETH1_TXD1: R208.1(P1) U17.5(TXD_1)
PRU2ETH1_TXD2: R210.1(P1) U17.6(TXD_2)
PRU2ETH1_TXD3: R207.1(P1) U17.7(TXD_3)
PRU2ETH1_TXEN: R115.2(P2) R205.1(P1) U17.3(TX_EN)
PRU2ETHER0_RDN: J6.2 R182.2(P2) U15.9(RD-)
PRU2ETHER0_RDP: J6.1 R183.2(P2) U15.10(RD+)
PRU2ETHER0_TDN: J6.6 R184.2(P2) U15.11(TD-)
PRU2ETHER0_TDP: J6.5 R185.2(P2) U15.12(TD+)
PRU2ETHER1_RDN: J8.6 R224.2(P2) U17.9(RD-)
PRU2ETHER1_RDP: J8.5 R225.2(P2) U17.10(RD+)
PRU2ETHER1_TDN: J8.2 R226.2(P2) U17.11(TD-)
PRU2ETHER1_TDP: J8.1 R227.2(P2) U17.12(TD+)
QSPI_CLK: R23.1(P1) R24.1(P1) R31.2(P2)
RSTOUTTOPMIC: R36.1(P1) R793.2(P2) ; also on sheet 19
SPIMEM_CLK: R31.1(P1) U4.16(SCK)
SPIMEM_CSn: R30.1(P1) U4.7(~{CS})
SPIMEM_D0: R25.1(P1) U4.15(SI/IO0)
SPIMEM_D1: R26.1(P1) U4.8(SO/IO1)
SPIMEM_D2: R22.1 R27.1(P1) U4.9(~{WP}/IO2)
SPIMEM_D3: R28.1(P1) R799.1 U4.1(~{HOLD}/IO3)
SYS_RESETn: R29.2(P2) R918.1(P1) R922.1(P1) ; also on sheet 5 34
SYS_WARMRESETn: C570.1 R2.1 R7.2(P2) R915.2(P2) R918.2(P2) R919.2(P2) U47.4(Y) U97.4(Y) ; also on sheet 2 15
VADD33_PRU2ETH0: C137.1 R180.2(P2) U15.14(AVDD33)
VADD33_PRU2ETH1: C142.1 R222.2(P2) U17.14(AVDD33)
VETH0_AVDDH: C153.1 C154.1 C157.1 FB1.2 Q7.3(S) U21.1(AVDDH) U21.12(AVDDH) U21.47(AVDDH)
VETH0_AVDDL: C161.1 C162.1 FB4.2 U21.4(AVDDL) U21.9(AVDDL)
VETH0_AVDDL_PLL: C163.1 C164.1 C165.1 FB2.2 U21.44(AVDDL_PLL)
VETH0_AVDDL_PMOS: C158.1 FB2.1 FB3.1 FB4.1 Q7.2(D1) Q7.4(D2)
VETH0_DVDDH: C155.1 C156.1 C171.1 D3.1(Cathode) R278.1(P1) R279.2 R280.2(P2) R297.2(P2) R299.1 R301.1 R306.1 R309.1 U21.16(DVDDH) U21.34(DVDDH) U21.40(DVDDH) U22.5(VCC)
VETH0_DVDDL: C159.1 C160.1 FB3.2 U21.14(DVDDL) U21.18(DVDDL) U21.23(DVDDL) U21.26(DVDDL) U21.30(DVDDL) U21.39(DVDDL)
VETH1_AVDDH: C176.1 C177.1 C178.1 FB5.2 Q8.3(S) U24.1(AVDDH) U24.12(AVDDH) U24.47(AVDDH)
VETH1_AVDDL: C182.1 C183.1 FB8.2 U24.4(AVDDL) U24.9(AVDDL)
VETH1_AVDDL_PLL: C184.1 C185.1 C186.1 FB6.2 U24.44(AVDDL_PLL)
VETH1_AVDDL_PMOS: C179.1 FB6.1 FB7.1 FB8.1 Q8.2(D1) Q8.4(D2)
VETH1_DVDDH: C174.1 C175.1 C192.1 D4.1(Cathode) R322.1(P1) R324.2(P2) R342.2(P2) R343.1 R345.1 R352.1 R353.1 R364.1 U24.16(DVDDH) U24.34(DVDDH) U24.40(DVDDH) U26.5(VCC)
VETH1_DVDDL: C180.1 C181.1 FB7.2 U24.14(DVDDL) U24.18(DVDDL) U24.23(DVDDL) U24.26(DVDDL) U24.30(DVDDL) U24.39(DVDDL)
VPP_EN: J1_1.4 R2_1.1 U1_1.3(EN)
VRTC_OUT: R645.2 ; also on sheet 11 19 22
VSDMMC: C483.1 C485.1 C486.1 C487.1 R397.2 R398.2 R399.2 R400.2 R401.2 R408.2(P2) R644.2 ; also on sheet 19 22
N10692191: R11.2(P2) SW2.3 SW2.4 U48.1
N10692247: C5.1 R11.1(P1) R914.1 U97.2(A)
N12123192: J10.11 R293.2
N12123204: J10.14 R296.2
N12138943: R298.1 U21.48(ISET)
N12139138: TP16.1 U21.41(CLK125_NDO)
N17144335: R29.1(P1) U4.3(~{RESET})
N17156111: C172.2 R305.2(P2) U23.1(Xin/CLK) Y3.2
N17156113: C173.2 R305.1(P1) R308.2(P2) Y3.1
N17156222: R308.1(P1) U23.14(XOUT)
N17156522: R310.1 U23.11(Y1)
N17156525: R313.1 U23.9(Y2)
N17156528: R315.1 U23.8(Y3)
N17156983: R314.1(P1) U23.12(S2/SCL)
N17156986: R312.1(P1) U23.13(S1/SDA)
N17569906: J12.11 R337.2
N17569909: J12.14 R340.2
N17569918: R341.1 U24.48(ISET)
N17569921: TP17.1 U24.41(CLK125_NDO)
N17570093: C193.2 R349.2(P2) U25.1(Xin/CLK) Y4.2
N17570094: C194.2 R349.1(P1) R351.2(P2) Y4.1
N17570107: R351.1(P1) U25.14(XOUT)
N17570112: R354.1 U25.11(Y1)
N17570113: R357.1 U25.9(Y2)
N17570114: R359.1 U25.8(Y3)
N17570122: R358.1(P1) U25.12(S2/SCL)
N17570123: R356.1(P1) U25.13(S1/SDA)
N17594977: C134.1 C135.1 C136.1 C138.1 U15.13(PFBIN1) U15.15(PFBOUT) U15.24(PFBIN2)
N17595032: R190.1 R195.1(P1) U70.1(A)
N17595048: R186.2(P2) U15.16(RBIAS)
N17595072: J6.9 R189.1(P1)
N17595076: J6.11 R161.1(P1)
N17595078: J6.12 R176.1(P1)
N17596821: J8.11 R203.1(P1)
N17596823: C147.1 C148.1 C149.1 C150.1 U17.13(PFBIN1) U17.15(PFBOUT) U17.24(PFBIN2)
N17596838: J8.10 R957.1(P1)
N17596847: R230.2(P2) U1.C17(MCASP3_AXR1/PR2_MII1_RXLINK)
N17596886: J8.9 R214.1(P1)
N17596899: R233.1 R234.1(P1) U71.1(A)
N17596976: R228.2(P2) U17.16(RBIAS)
N17596979: J8.12 R218.1(P1)
N17597002: R230.1(P1) R231.2(P2) R957.2(P2) R958.1(P1)
N18733248: R497.1(P1) U1.AD14(RTC_OSC_XO)
N18733249: C247.1 R497.2(P2) Y6.4
N18733252: C246.1 R927.2(P2) U1.AE14(RTC_OSC_XI) Y6.1
N18733262: R499.2(P2) U1.AF14(RTC_ISO)
N18733263: R498.1 R500.1(P1) U39.4(Y)
N18733273: R500.2(P2) R926.2(P2) U1.AB17(RTC_PORZ)
N18733274: R929.2(P2) U1.Y11(ON_OFF)
N18733276: R923.1(P1) TP19.1 U1.AD17(WAKEUP0)
N19425975: R7.1(P1) U1.E23(RESETn)
N19426030: R8.1(P1) U1.D21(NMI_DSP)
N19426454: R569.1(P1) U1.AC15(XI_OSC1)
N20204523: R643.1(P1) U1.AC17(WAKEUP1)
N22734288: R917.1 U2.4(Y) U98.2(B)
N22734327: C4.1 R10.1 R916.1(P1) U2.2(A)
N22734777: R916.2(P2) SW1.3 SW1.4 U49.1
N22735118: R9.2(P2) U98.1(A)
N22762383: R925.1(P1) U1.AC16(WAKEUP3)
N22762388: R924.1(P1) U1.AB16(WAKEUP2)
N24757165: J6.10 R172.1(P1)

Not connected (* = marked no-connect by the designer): J6 7*; J8 7*; J10 2; J12 2; U1 AC13(XO_OSC1); U2 1(NC)*; U4 4(NC4)* 5(NC5)* 6(NC6)* 11(NC11)* 12(NC12)* 13(NC13)*; U15 22(XO)*; U17 22(XO)*; U21 45(XO)*; U22 1(NC)*; U23 2(S0)* 4(Vctr)*; U24 45(XO)*; U25 2(S0)* 4(Vctr)*; U26 1(NC)*; U30 4(NC1)* 9(NC2)*; U39 1(NC)*; U47 1(NC)*; U97 1(NC)*; Y6 2* 3*

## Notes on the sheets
sheet 26
- Note: MDIO Address = 0x01
- Real-Time
  Development
  Header
sheet 27
- Note: MDIO Address = 0x00
- Real-Time
  Development
  Header
sheet 29
- Catalog Processors - Vpp Programming Circuit
sheet 31
- User Warm Reset Switch
sheet 32
- SD/MMC1 Connector
